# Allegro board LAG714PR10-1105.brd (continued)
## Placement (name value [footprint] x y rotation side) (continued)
RW5  0_0805_5%  [R_0805]  67.98 125.12 270 top
RW6  0_0402_5%  [R_0402]  70.33 132.41 270 top
RW9  0_0402_5%  [R0402_0OHM]  81.12 133.64 90 bottom
RW10  0_0402_5%  [R0402_0OHM]  71.22 132.41 270 top
RW11  0_0402_5%  [R0402_0OHM]  68.28 135.44 0 top
RW12  0_0402_5%  [R0402_0OHM]  71.61 135.44 180 top
RX1  33_0402_5%  [R_0402]  118.63 38.64 180 bottom
RX2  33_0402_5%  [R_0402]  117.55 40.6 180 bottom
RX3  33_0402_5%  [R_0402]  117.59 41.66 180 bottom
RX4  10K_0402_5%  [R_0402]  134.05 55.45 90 bottom
RX5  10K_0402_5%  [R_0402]  113.08 36.95 180 bottom
RX6  0_0402_5%  [R_0402]  115.99 38.46 90 top
RX7  0_0402_5%  [R_0402]  115.1 38.46 90 top
RX8  0_0402_5%  [R_0402]  108.57 39.68 180 bottom
RX9  0_0402_5%  [R_0402]  111.36 36.95 180 bottom
RX10  0_0402_5%  [R_0402]  108.57 40.51 180 bottom
RZ1  22.1K_0402_1%  [R_0402]  151.51 66.88 90 top
RZ2  0_0402_5%  [R_0402]  149.98 55.84 0 top
RZ3  49.9K_0402_1%  [R_0402]  150.05 56.78 90 top
RZ4  0_0603_5%  [R_0603]  148.13 69.57 180 top
SW1  TST71-N-220-T170-S017_2P  [SW_TST71-N-220-T170-S017_2P]  221.21 61.99 0 top
TL1  MHPC_NS681611H  [BOTH_NS0013LF_16P]  17.03 73.13 270 top
TL2  MHPC_NS681611H  [BOTH_NS0013LF_16P]  17.03 64.24 90 bottom
TP3  PAD  [TPC12]  108.92 93.28 180 bottom
TP4  PAD  [TPC12]  109.99 94.1 180 bottom
TP5  PAD  [TPC12]  119.58 90.57 0 top
TP6  PAD  [TPC12]  118.31 90.6 0 top
TP7  PAD  [TPC12]  139.05 105.14 180 bottom
TP8  PAD  [TPC12]  133.92 83.16 0 top
TP9  PAD  [TPC12]  133.52 84.44 0 top
TP10  PAD  [TPC12]  117.16 67.72 0 top
TP11  PAD  [TPC12]  110.32 69.25 180 bottom
TP12  PAD  [TPC12]  111.91 64.84 180 bottom
TP13  PAD  [TPC12]  120.28 64.83 0 top
TP14  PAD  [TPC12]  141.41 94.93 180 bottom
TP15  PAD  [TPC12]  137.96 90.66 180 bottom
TP16  PAD  [TPC12]  139.43 89.14 180 bottom
TP17  PAD  [TPC12]  137.98 89.31 180 bottom
TP18  PAD  [TPC12]  139.23 90.41 180 bottom
TP19  PAD  [TPC12]  112.3 103.48 180 bottom
TP20  PAD  [TPC12]  109.39 103.63 180 bottom
TP21  PAD  [TPC12]  109.98 102.34 180 bottom
TP22  PAD  [TPC12]  110.77 104.07 180 bottom
TP23  PAD  [TPC12]  121.98 66.86 0 top
TP24  PAD  [TPC12]  121.65 64.91 0 top
TP25  PAD  [TPC12]  116.97 56.86 180 bottom
TP26  PAD  [TPC12]  117.67 62.38 0 top
TP27  PAD  [TPC12]  110.61 57.82 180 bottom
TP28  PAD  [TPC12]  116.37 62.82 0 top
TP29  PAD  [TPC12]  116.43 61.45 0 top
TP30  PAD  [TPC12]  115.1 103.49 180 bottom
TP31  PAD  [TPC12]  113.75 103.61 180 bottom
TP32  PAD  [TPC12]  131.45 78.06 0 top
TP33  PAD  [TPC12]  121.32 77.83 0 top
TP38  PAD  [TPC12]  119.66 72.31 0 top
TP39  PAD  [TPC12]  120.73 71.45 0 top
TP44  PAD  [TPC12]  27.97 68.13 0 top
TP46  PAD  [TPC12]  196.2 62.49 180 bottom
TP48  PAD  [TPC12]  19.11 88.76 90 top
TP49  PAD  [TPC12]  22.2 87.37 90 bottom
TP74  PAD  [TPC12]  92.05 51.54 0 top
TP75  PAD  [TPC12]  120.82 68.64 0 top
TP76  PAD  [TPC12]  119.24 65.59 0 top
TP77  PAD  [TPC12]  119.59 67.76 0 top
TP79  PAD  [TPC12]  124.79 57.51 180 bottom
TPC1  PAD  [TPC12]  140.46 90.84 270 bottom
TPC2  PAD  [TPC12]  138.62 93.31 180 bottom
TPC3  PAD  [TPC12]  139.15 91.78 180 bottom
TPC4  PAD  [TPC12]  140.45 92.24 180 bottom
TPC5  PAD  [TPC12]  145.65 97.9 0 top
TPC6  PAD  [TPC12]  137.98 94.5 180 bottom
TPC7  PAD  [TPC12]  139.98 62.16 180 bottom
TPC8  PAD  [TPC12]  109.88 54.57 180 bottom
TPC9  PAD  [TPC12]  113.37 54.44 180 bottom
TPC10  PAD  [TPC12]  139.53 100.54 180 bottom
TPC11  PAD  [TPC12]  139.51 101.84 180 bottom
TPC12  PAD  [TPC12]  133.26 99.83 0 top
TPC13  PAD  [TPC12]  140.8 105.14 180 bottom
TPC14  PAD  [TPC12]  134.07 102.6 0 top
TPC15  PAD  [TPC12]  136.69 105.06 180 bottom
TPC16  PAD  [TPC12]  135.75 104.2 180 bottom
TPC17  PAD  [TPC12]  136.61 103.26 180 bottom
TPC18  PAD  [TPC12]  132.52 97.39 0 top
TPC19  PAD  [TPC12]  132.93 96.12 0 top
TPC20  PAD  [TPC12]  134.76 105.01 180 bottom
TPC21  PAD  [TPC12]  133 102.45 180 bottom
TPC22  PAD  [TPC12]  134.83 103.31 180 bottom
TPC23  PAD  [TPC12]  133.49 104.86 180 bottom
TPC24  PAD  [TPC12]  131.68 102.4 180 bottom
TPC25  PAD  [TPC12]  132.22 105.11 180 bottom
TPC26  PAD  [TPC12]  132.24 103.56 180 bottom
TPC27  PAD  [TPC12]  133.59 103.59 180 bottom
TPC28  PAD  [TPC12]  133.84 98.69 0 top
TPC29  PAD  [TPC12]  134.12 97.32 0 top
TPC30  PAD  [TPC12]  133.92 94.32 0 top
TPC31  PAD  [TPC12]  137.91 92.21 180 bottom
TPC32  PAD  [TPC12]  101 60.19 0 top
TPC33  PAD  [TPC12]  141.13 102.48 180 bottom
TPS1  PAD  [TPC12]  139.95 60.36 180 bottom
TPS2  PAD  [TPC12]  118.5 66.89 0 top
TPS3  PAD  [TPC12]  149.53 51.09 0 top
TPS4  PAD  [TPC12]  108.77 68.77 180 bottom
TPS5  PAD  [TPC12]  95.35 40.57 0 top
TPS6  PAD  [TPC12]  118.61 69.53 0 top
TPS8  PAD  [TPC12]  223.43 65.67 0 top
U1  -  [SY6288C20AAC_SOT23-5]  220.06 55.87 0 top
U2  -  [NCT7718W_MSOP8]  103.36 123.83 90 bottom
U3  -  [SY6288C20AAC_SOT23-5]  210.41 42.8 0 top
UA1  -  [ALC3246-CG_MQFN48_6X6]  32.83 11.05 180 top
UC1  SKL-U_BGA1356  [SKL-U_BGA_1356P-T]  136.55 59.59 270 bottom
UC2  -  [74AUP1G07GW_TSSOP5]  106.24 117.23 90 top
UC3  W25Q128JVSIQ_SO8  [W25Q128FVSIQ_SO8]  129.74 45.31 270 bottom
UC4  -  [SN74AHC1G08DCKR_SC70-5]  120.37 44.61 180 bottom
UC5  -  [SN74AHC1G08DCKR_SC70-5]  98.76 55.11 0 top
UC6  -  [74AUP1G07GW_TSSOP5]  121.69 39.19 270 top
UC7  -  [74AUP1G07GW_TSSOP5]  145.88 104.36 180 top
UC9  -  [SN74AHC1G08DCKR_SC70-5]  149.53 52.54 0 top
UE1  -  [MEC1416-NU-D0_VTQFP128_14X14]  33.58 75.63 0 top
UE2  -  [NL17SZ06DFT2G_SC70-5]  48.18 57.43 0 top
UL1  RTL8106E-CG_QFN32_4X4  [RTL8106E-CG_QFN32_4X4-S]  23.08 83.54 0 top
UL2  -  [SY6288C20AAC_SOT23-5]  24.74 97.92 0 top
UM1  THGBMBG8D4KBAIR_VFBGA153  [THGBMBG8D4KBAIRNHDI_VFBGA_153P]  144.52 34.11 90 top
UM2  -  [74AUP1G07GW_TSSOP5]  152.54 28.52 90 top
US1  -  [LNG2DMTR_LGA12_2X2]  190.45 40.77 180 top
US2  -  [SY6288D20AAC_SOT23-5]  178.97 36.96 180 bottom
UU1  -  [SY6288D20AAC_SOT23-5]  20.17 42.67 90 bottom
UU3  -  [SY6288D20AAC_SOT23-5]  198.96 38.86 180 bottom
UX1  -  [NPCT650VB2YX_QFN32_5X5]  110.1 39.17 0 bottom
UZ1  TPS22967DSGR_SON8_2X2  [TPS22967DSGR_SON8_2X2-S]  149.25 66.01 90 top
UZ2  EM5201V DFN3X3 8P  [TPS22961DNYR_WSON8]  148.93 59.19 90 top
UZ3  -  [EM5209VF_DFN14_3X2]  128.17 136.49 180 top
YC1  24MHZ_12PF_X3G024000DC1H  [Y_X3G024000DC1H_4P]  143.93 77.54 90 bottom
YC2  32.768KHZ_9PF_X1A000141000200  [Y_X1A000141000200_2P]  105.84 57.11 180 top
YC3  24MHZ_12PF_X3G024000DC1H  [Y_X3G024000DC1H_4P]  146.65 55.36 270 bottom
YE1  32.768KHZ_9PF_X1A000141000200  [Y_X1A000141000200_2P]  37.76 82.32 180 top
YL1  25MHZ_10PF_7V25000014  [Y_7V25000014_4P]  16.2 87.41 270 top

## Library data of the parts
C1-C3 C5-C12 C14-C19 C21 C23 C26 C27 C31-C41 CA2 CA4-CA7 CA9 CA10 CA12-CA17 CA20-CA23 CA26-CA31 CA34-CA38 CA40-CA42 CC1-CC5 CC8-CC15 CC26-CC35 CC39-CC58 CC60-CC63 CC67 CC68 CC72 CC73 CC75 CC78 CC79 CC82 CC85-CC88 CC90 CC91 CD3-CD5 CD9-CD18 CD28-CD31 CD35 CD36 CD39-CD48 CD58 CD59 CE1-CE4 CE6-CE17 CE19-CE26 CE28 CE30-CE33 CE35 CI1-CI9 CL1-CL12 CL15 CL18-CL20 CL22-CL25 CM1-CM8 CS1-CS6 CS8-CS14 CS16-CS23 CS25-CS27 CS29 CT55-CT60 CU1-CU4 CU6 CU11 CW1-CW4 CW6-CW9 CX1-CX7 CZ1-CZ12 CZ21-CZ23 CZ25 EC2301 EC2302 EC2901 EC2902 EC3001-EC3003 PC1-PC4 PC11-PC15 PC301 PC302 PC305-PC308 PC315 PC501 PC502 PC505-PC508 PC515-PC517 PC1805-PC1807 PC2503-PC2505 PCA03 PCA04 PCA05 PCA06 PCA117 PCA118 PCB01 PCB02 PCB07 PCB08 PCB09-PCB12 PCB14-PCB17 PCB22 PCB25 PCB26 PCB28-PCB32 PCC05 PCC6 PCG05 PCG06 PCG07 PCG08 PCG10 PCG11 PCG147 PCG148 PCH01 PCH02 PCH09-PCH12 PCH14-PCH16 PCI05 PCI06 PCI07 PCI08 PCI10 PCI11 PCI21 PCI22 PCI27 PCI28 PCI30 PCI31 PCI164 PCI165 PCM01 PCM02 PCM11 PCM12 PCM15-PCM19 PCM22 PCM23 PCZ01 PCZ02 PCZ03 PCZ04 PCZ05 PCZ06 PCZ07 PCZ08 PCZ09-PCZ33 PCZ35 PCZ36 = C_0402
C4 C22 C30 CA1 CA3 CA11 CA24 CA25 CA32 CA33 CC36-CC38 CC59 CC76 CC77 CC83 CC84 CD1 CD2 CD6-CD8 CD19-CD26 CD32-CD34 CD37 CD38 CD49-CD56 CE5 CS7 CS15 CS35 CS36 CU8 CU9 CU13 CU14 CU17 CW5 PC309 PC509 PC1801-PC1804 PCA07 PCA08 PCA09 PCA101-PCA109 PCB13 PCB18 PCB27 PCC01 PCC02 PCC03 PCC04 PCG09 PCG12 PCG101-PCG133 PCH05 PCH06 PCH07 PCH08 PCH13 PCI09 PCI12 PCI29 PCI32 PCI101-PCI128 PCM05 PCM06 PCM07 PCM08 PCM09 PCM10 PCM13 PCM14 PCM20 PCM21 PCZ34 = C_0603
CC6 CC7 CC17 CC18 CC69-CC71 CU5 CU16 PCA110-PCA116 PCG134-PCG146 PCI129-PCI163 = C_0201
CD27 PCG171 PCG172 PCI171-PCI173 = C_D2
CL13 = C_1206
CS24 CS30 CS33 CS34 PC303 PC304 PC310-PC314 PC503 PC504 PC510-PC514 PC2501 PC2502 PCA01 PCA02 PCB03 PCB04 PCB05 PCB06 PCB19-PCB21 PCB23 PCB24 PCG01 PCG02 PCG03 PCG04 PCH03 PCH04 PCI01 PCI02 PCI03 PCI04 PCI23-PCI26 PCM03 PCM04 = C_0805
CU10 CU15 = C_A
D1 = BAS40C_SOT23-3
D3 D4 DA3 = BAT54C-7-F_SOT23-3
D5 D6 = RB551V-30_SOD323-2
D7 DZ2-DZ5 = RB751S40T1G_SOD523-2
DA1 DA2 DA4 DA7 ED2901 = L03ESDL5V0CC3-2_SOT23-3
DA5 = AZ5123-02SPR7G_SOT23-3
DA6 EU2602 EU2604 EU2701 EU4012 = AZC199-02SPR7G_SOT23-3
DE1 = AZ5125-01HPR7G_SOD523-2
DI1 = BAW56W_SOT323-3
EU2601 EU2603 = L05ESDL5V0NA-4_SLP2510P8-10-9
F1 = F_SMD1812P150TF-24
F2 = F_SMD1812P110TF-24
F3 = F_MF-NSMF050-2
FD1-FD4 = FIDUCIAL_C40M80
FI1 = F_1206L150PR
H1-H5 H7 = H_3P0
H6 = H_5P0
H8 = H_3P3
H12 = H_3P2
H13 = H_3P0X4P0
H14 = H_5P6N
HCPU1 HCPU4 = H_4P0X3P7
HCPU2 = H_3P7
HCPU3 = H_4P0
JCMOS1 = SHORTPADS: User Part Number: PART#
JDEG1 JESPI1 = JXT_FP241AH-010GAAM_10P
JDIMM1 = LOTES_ADDR0206-P001A02_260P
JDIMM2 = LOTES_ADDR0205-P001A02_260P
JEDP1 = ACES_51540-04001-P01_40P
JFAN1 JSPK1 = ACES_50224-00401-001_4P
JFP = ACES_51522-00601-001_6P-NPM
JFP1 = ACES_51522-00801-001_8P
JHDD1 = ACES_51625-01201-001_12P
JHDMI1 = ACON_HMRF6-AK120C_19P-T
JHP1 = YUQIU_PJ753-F07J1BE-B_7P-T
JIOB1 = ACES_51524-0160N-001_16P
JKB1 = HEFEN_AFB02-S30F1A-HF_30P-T
JKBBL1 = ACES_51575-00401-001_4P
JLAN1 = SINGA_2RJ3076-078211F_8P-T
JODD1 = ACES_50673-0120N-P01_12P
JP1 JP5 JP6 JP10 PJP2 PJP501 PJP1802 PJPG01 = JUMP_43X79
JP2 JP4 JP11 PJP301 PJP1801 PJP2501 PJP2502 PJPA01 PJPH01 PJPM01 PJPM03 = JUMP_43X39
JPWR1 = JXT_FP226H-004S1AM_4P
JSSD1 = LCN_DAN05-67306-0103_75P
JTP1 = ACES_51524-0080N-001_8P
JUSB1 JUSB2 = ACON_TARAN-9R1391_9P
JVGA = ACES_51625-01601-001_16P-T
JWLAN1 = LCN_DAN05-67306-0100_75P
L1 L2 = MURAT_BLM15BD601SN1D_2P
L3 LU1 LU4 LU8 LU9 = INPAQ_MCM1012B900F06BP_4P
L4 = INPAQ_MCM1012B900F06BP_4P-NPM
L5 = MURAT_BLM15PX221SN1D_2P
LED1 = LED_LTW-295DSKS-5A_4P
LI1-LI4 LU2 LU3 LU5 LU6 = INPAQ_HCM1012GH900BP_4P-NPM
PBATT1 = ACES_50458-01001-P01_10P-T
PCG13 PCI13 = C_EEFCX1E330R
PCG14 PCI14 = C_6P3X4P5-NPM
PD1 PD5 PD6 = TVNST52302AB0_SOT523-3
PD2 PD3 = BAV99W_SC70-3
PD501 = SDMK0340L-7-F_SOD323-2
PDB01 = LRB715FT1G_SOT323-3
PHZ01 PHZ02 PHZ03 PHZ04 PHZ05 PR1 PR3-PR7 PR31 PR33-PR45 PR302-PR304 PR306-PR308 PR504 PR506 PR508-PR511 PR1802 PR1803 PR1805 PR1807 PR2502-PR2504 PRB03 PRB04 PRB06 PRB07 PRB08 PRB09-PRB11 PRB13 PRB14 PRB19-PRB21 PRB24 PRB25 PRB29-PRB40 PRB42 PRB43 PRG02 PRH02 PRH03 PRH04 PRH05 PRH08 PRH09 PRH11 PRH12 PRI02 PRI22 PRM03 PRM06 PRM07 PRM10 PRM11 PRZ01 PRZ04 PRZ05 PRZ06 PRZ08 PRZ10 PRZ11 PRZ15 PRZ16 PRZ19-PRZ21 PRZ23 PRZ24 PRZ26-PRZ28 PRZ30-PRZ33 PRZ35-PRZ43 PRZ45 PRZ46 PRZ48-PRZ52 PRZ55-PRZ58 PRZ60 PRZ61 PRZ64-PRZ69 R1 R2 R5 R9 R10 R19-R35 R38-R43 R46-R50 R57 R65-R69 R72 R74-R76 R78-R80 RA3 RA7-RA12 RA23-RA34 RA41-RA43 RC1-RC12 RC14 RC15 RC18-RC28 RC33-RC42 RC44-RC47 RC51-RC58 RC63-RC69 RC72-RC78 RC80 RC82 RC85-RC96 RC102-RC105 RC108-RC115 RC117-RC134 RC136-RC148 RC150-RC157 RC159 RC160 RC163 RC164 RC175-RC182 RC188 RC194-RC199 RC205 RC207 RC209 RC211-RC213 RC224 RC443 RD1-RD3 RD7 RD9-RD13 RD15 RD17 RD19-RD24 RE1 RE3 RE4 RE6 RE8-RE21 RE23 RE25 RE29 RE32 RE40 RE41 RE43 RE45 RE46 RE48 RE49 RE51-RE59 RE62 RE65 RE67 RE68 RE70 RE91 RE92 RH1 RI1-RI16 RL2-RL4 RL6-RL9 RL17 RM3 RM12-RM25 RM27 RS2-RS5 RU3-RU6 RU9-RU12 RW6 RX1-RX10 RZ1-RZ3 = R_0402
PJP1 PJP3 PJPI01 = JUMP_43X79-NPM
PJP302 PJP502 PJPH02 PJPM02 = JUMP_43X118
PJPB01 = JUMP_43X118-NPM
PJPDC1 = ACES_50458-00601-001_6P-T
PL1 PL4 PL511 PLB02 PLG11 PLI11 = 5A_Z150_1210_2P
PL2 = 5A_Z150_1210_2P-NPM
PL3 = MURAT_BLM15AG102SN1D_2P
PL301 PL501 PLB01 PLH01 PLM01 = L_7X7X3_M_2P
PL311 PL1811 PLH11 PLM11 = TAI-T_HCB2012KF-121T50_2P
PL1801 = L_5X5X3_M_2P
PLA01 = L_5X5X3_M
PLG01 PLI01 PLI02 = L_7X7X4_M
PQ1 = FDV301N-G_SOT23-3
PQ2 = MMST3904-7-F_SOT323-3
PQ11 PQB03 PQB04 QI3 = DMN65D8LW-7_SOT323-3
PQ12 PQ13 = DMN65D8LDW-7_SOT363-6
PQA01 PQM01 = AON7934_DFN3X3A8-10
PQB01 PQB02 = AON7702L_DFN8-5
PQB05 PQB06 = RUM002N02GT2L_VMT3
PQB07 = LTC015EUBFS8TL_UMT3F
PQB08 = LMUN5113T1G_SOT323-3
PQB11-PQB13 = TPCA8059-H_PPAK56-8-5
PR32 PR305 PR505 PR1804 PRA02 PRB22 PRB27 PRG03 PRH07 PRI03 PRI23 PRM01 = R_1206
PR301 PR501 PRB12 PRB15 RA4 RA39 RC17 RC169-RC171 RC173 RC174 RE2 RE7 RE50 RE66 RL5 = R0603_0OHM
PR502 PR503 PR507 PR1801 PR2501 PRB05 PRB17 PRB18 PRB23 PRB26 PRB41 PRH01 PRM08 PRM09 PRZ03 PRZ07 PRZ14 PRZ18 PRZ22 PRZ34 PRZ47 PRZ53 PRZ59 PRZ63 R6 R8 R45 R77 RA2 RA5 RA6 RA17 RA18 RA36 RA37 RA40 RC97 RC99 RC106 RC107 RD4-RD6 RD8 RD14 RD16 RD18 RE28 RE37 RE42 RE47 RE60 RE61 RE63 RE81 RL13 RS1 RW9-RW12 = R0402_0OHM
PRA01 PRB16 PRB28 PRG01 PRH06 PRI01 PRI21 PRM02 PRM04 PRM05 PRZ13 PRZ25 PRZ29 PRZ44 R4 R7 R11-R13 R16 R36 R37 RC149 RL1 RL14 RL15 RL19 RL20 RM1 RM2 RZ4 = R_0603
PRB01 PRB02 = R_1206_4P
PRC01 PRC02 PRC03 PRC7 R3 RW3 RW5 = R_0805
PRC04 PRC05 PRC06 = SOLDER_PREFORMS_0603-NPM
PU301 = SY8286BRAC_QFN20_3X3
PU501 = SY8288CRAC_QFN20_3X3
PU1801 = RT8061AZQW_WDFN10_3X3
PU2501 = RT9059GSP_SO8
PUA01 = NCP81253MNTBG_DFN8_2X2
PUB01 = ISL95520HRZ-T_QFN32_4X4-S
PUG01 PUI01 PUI02 = NCP302045MNTXG_PQFN33_5X5
PUH01 = RT6226AGQUF_UQFN12_3X3
PUM01 = RT8207PGQW_WQFN20_3X3
PUZ01 = NCP81218MNTXG_QFN48_6X6
Q1 Q12 Q13 QC2 QI1 = 2N7002K_SOT23-3
Q4 Q24 = L2N7002WT1G_SC-70-3
Q6 Q8 Q9 Q22 QA1 = LN2306LT1G_SOT23-3
Q7 Q18 Q19 = DDTA144VCA-7-F_SOT23-3
Q10 Q11 Q17 Q25 QC1 QI2 QS1 = DMN66D0LDW-7_SOT363-6
Q14 = LMBT3904LT1G_SOT23-3
Q15 = SI2301CDS-T1-GE3_SOT23-3
Q23 = LP2301ALT1G_SOT23-3
R17 R18 RU1 RU2 RU7 RU8 RU13-RU16 = R_0402-NPM
RA1 RA22 = R0805_0OHM
RA13-RA16 = MURAT_BLM15PD600SN1D_2P
RA35 RA38 = MURAT_BLM15PX330SN1D_2P
RP1 RP2 RPC1-RPC3 RPE1-RPE7 RPI1 RPI2 RPM1 RPM2 = RP_0804_8P4R
SW1 = SW_TST71-N-220-T170-S017_2P
TL1 TL2 = BOTH_NS0013LF_16P
TP3-TP33 TP38 TP39 TP44 TP46 TP48 TP49 TP74-TP77 TP79 TPC1-TPC33 TPS1-TPS6 TPS8 = TPC12
U1 U3 UL2 = SY6288C20AAC_SOT23-5
U2 = NCT7718W_MSOP8
UA1 = ALC3246-CG_MQFN48_6X6
UC1 = SKL-U_BGA_1356P-T
UC2 UC6 UC7 UM2 = 74AUP1G07GW_TSSOP5
UC3 = W25Q128FVSIQ_SO8
UC4 UC5 UC9 = SN74AHC1G08DCKR_SC70-5
UE1 = MEC1416-NU-D0_VTQFP128_14X14
UE2 = NL17SZ06DFT2G_SC70-5
UL1 = RTL8106E-CG_QFN32_4X4-S
UM1 = THGBMBG8D4KBAIRNHDI_VFBGA_153P
US1 = LNG2DMTR_LGA12_2X2
US2 UU1 UU3 = SY6288D20AAC_SOT23-5
UX1 = NPCT650VB2YX_QFN32_5X5
UZ1 = TPS22967DSGR_SON8_2X2-S
UZ2 = TPS22961DNYR_WSON8
UZ3 = EM5209VF_DFN14_3X2
YC1 YC3 = Y_X3G024000DC1H_4P
YC2 YE1 = Y_X1A000141000200_2P
YL1 = Y_7V25000014_4P

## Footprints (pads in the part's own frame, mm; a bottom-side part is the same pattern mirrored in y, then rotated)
2N7002K_SOT23-3
  oval 1.016x1.524 smd: 1(0,0) 2(0.965,2.083) 3(-0.965,2.083)
5A_Z150_1210_2P
  rect 0.991x2.997 smd: 1(0,0) 2(2.7,0)
5A_Z150_1210_2P-NPM
  rect 0.991x2.997 smd: 1(0,0) 2(2.7,0)
74AUP1G07GW_TSSOP5
  oval 0.381x1.346 smd: 1(0,0) 2(0.65,0) 3(1.3,0) 4(1.3,1.79) 5(0,1.79)
ACES_50224-00401-001_4P
  oval 0.61x1.549 smd: 1(0,0) 2(1,0) 3(2,0) 4(3,0)
  rect 1.194x1.803 smd: 5(4.3,-3.875) 6(-1.3,-3.875)
ACES_50458-00601-001_6P-T
  oval 0.559x1.6 smd: 1(0,0) 2(2,0) 3(4,0) 4(6,0) 5(8,0) 6(10,0)
  rect 1.295x2.057 smd: 7(-3.1,-5.175) 8(13.1,-5.175)
ACES_50458-01001-P01_10P-T
  oval 0.559x1.803 smd: 1(0,0) 2(2,0) 3(4,0) 4(6,0) 5(8,0) 6(10,0) 7(12,0) 8(14,0) 9(16,0) 10(18,0)
  rect 1.295x2.057 smd: 11(-3.1,-5.275) 12(21.1,-5.275)
ACES_50673-0120N-P01_12P
  oval 0.61x1.397 smd: 1(0,0) 2(0,3) 3(-1,0) 4(-1,3) 5(-2,0) 6(-2,3) 7(-3,0) 8(-3,3) 9(-4,0) 10(-4,3) 11(-5,0) 12(-5,3) 13(-6,0) 14(-6,3) 15(-7,0) 16(-7,3) 17(-8,0) 18(-8,3) 19(-9,0) 20(-9,3) 21(-10,0) 22(-10,3) 23(-11,0) 24(-11,3)
  rect 1.702x2.388 smd: 25(-13.25,1.5) 26(2.25,1.5)
ACES_51522-00601-001_6P-NPM
  oval 0.305x1.295 smd: 1(0,0) 2(0.5,0) 3(1,0) 4(1.5,0) 5(2,0) 6(2.5,0)
  rect 2.489x1.905 smd: 7(-2.15,-3.3) 8(4.65,-3.3)
ACES_51522-00801-001_8P
  oval 0.305x1.295 smd: 1(0,0) 2(0.5,0) 3(1,0) 4(1.5,0) 5(2,0) 6(2.5,0) 7(3,0) 8(3.5,0)
  rect 2.489x1.905 smd: 9(5.65,-3.3) 10(-2.15,-3.3)
ACES_51524-0080N-001_8P
  oval 0.61x1.295 smd: 1(0,0) 2(1,0) 3(2,0) 4(3,0) 5(4,0) 6(5,0) 7(6,0) 8(7,0)
  rect 2.489x2.21 smd: 9(10,-3.05) 10(-3,-3.05)
ACES_51524-0160N-001_16P
  oval 0.61x1.295 smd: 1(0,0) 2(1,0) 3(2,0) 4(3,0) 5(4,0) 6(5,0) 7(6,0) 8(7,0) 9(8,0) 10(9,0) 11(10,0) 12(11,0) 13(12,0) 14(13,0) 15(14,0) 16(15,0)
  rect 2.159x2.21 smd: 17(-2.825,-3.05) 18(17.825,-3.05)
ACES_51540-04001-P01_40P
  oval 0.305x1.092 smd: 1(0,0) 2(0.5,0) 3(1,0) 4(1.5,0) 5(2,0) 6(2.5,0) 7(3,0) 8(3.5,0) 9(4,0) 10(4.5,0) 11(5,0) 12(5.5,0) 13(6,0) 14(6.5,0) 15(7,0) 16(7.5,0) 17(8,0) 18(8.5,0) 19(9,0) 20(9.5,0) 21(10,0) 22(10.5,0) 23(11,0) 24(11.5,0) 25(12,0) 26(12.5,0) 27(13,0) 28(13.5,0) 29(14,0) 30(14.5,0) 31(15,0) 32(15.5,0) 33(16,0) 34(16.5,0) 35(17,0) 36(17.5,0) 37(18,0) 38(18.5,0) 39(19,0) 40(19.5,0)
  rect 0.787x2.489 smd: 41(21.2,-3.6) 42(-1.7,-3.6)
ACES_51575-00401-001_4P
  oval 0.406x0.838 smd: 1(0,0) 2(1,0) 3(2,0) 4(3,0)
  rect 0.787x2.007 smd: 5(-2.2,-3.175) 6(5.2,-3.175)
ACES_51625-01201-001_12P
  oval 0.305x1.092 smd: 1(0,0) 2(0.5,0) 3(1,0) 4(1.5,0) 5(2,0) 6(2.5,0) 7(3,0) 8(3.5,0) 9(4,0) 10(4.5,0) 11(5,0) 12(5.5,0)
  rect 0.991x2.489 smd: 13(-1.8,-3.6) 14(7.3,-3.6)
ACES_51625-01601-001_16P-T
  oval 0.305x1.092 smd: 1(0,0) 2(-0.5,0) 3(-1,0) 4(-1.5,0) 5(-2,0) 6(-2.5,0) 7(-3,0) 8(-3.5,0) 9(-4,0) 10(-4.5,0) 11(-5,0) 12(-5.5,0) 13(-6,0) 14(-6.5,0) 15(-7,0) 16(-7.5,0)
  rect 0.991x2.489 smd: 17(1.8,-3.6) 18(-9.3,-3.6)
ACON_HMRF6-AK120C_19P-T
  round 0.813 hole 0.559: 1(0,0) 2(0.5,1.55) 3(1,0) 4(1.5,1.55) 5(2,0) 6(2.5,1.55) 7(3,0) 8(3.5,1.55) 9(4,0) 10(4.5,1.55) 11(5,0) 12(5.5,1.55) 13(6,0) 14(6.5,1.55) 15(7,0) 16(7.5,1.55) 17(8,0) 18(8.5,1.55) 19(9,0)
  oval 1.499x2.21 hole 0.889x1.6: 20(11.75,1.7) 21(13.65,-7.75) 22(-4.65,-6.5) 23(-2.75,1.7)
ACON_TARAN-9R1391_9P
  round 0.991 hole 0.711: 1(0,0) 2(-2.5,0) 3(-4.5,0) 4(-7,0) 5(-7.5,-1.5) 6(-5.5,-1.5) 7(-3.5,-1.5) 8(-1.5,-1.5) 9(0.5,-1.5)
  oval 1.397x3.2 hole 0.787x2.591: 10(-11.35,-2.38) 12(4.35,-2.38)
  oval 1.397x2.388 hole 0.787x1.803: 11(-11.35,-9.48) 13(4.35,-9.48)
ALC3246-CG_MQFN48_6X6
  oval 0.889x0.203 smd: 1(0,0) 2(0,-0.4) 3(0,-0.8) 4(0,-1.2) 5(0,-1.6) 6(0,-2) 7(0,-2.4) 8(0,-2.8) 9(0,-3.2) 10(0,-3.6) 11(0,-4) 12(0,-4.4) 25(6.1,-4.4) 26(6.1,-4) 27(6.1,-3.6) 28(6.1,-3.2) 29(6.1,-2.8) 30(6.1,-2.4) 31(6.1,-2) 32(6.1,-1.6) 33(6.1,-1.2) 34(6.1,-0.8) 35(6.1,-0.4) 36(6.1,0)
  oval 0.203x0.889 smd: 13(0.85,-5.25) 14(1.25,-5.25) 15(1.65,-5.25) 16(2.05,-5.25) 17(2.45,-5.25) 18(2.85,-5.25) 19(3.25,-5.25) 20(3.65,-5.25) 21(4.05,-5.25) 22(4.45,-5.25) 23(4.85,-5.25) 24(5.25,-5.25) 37(5.25,0.85) 38(4.85,0.85) 39(4.45,0.85) 40(4.05,0.85) 41(3.65,0.85) 42(3.25,0.85) 43(2.85,0.85) 44(2.45,0.85) 45(2.05,0.85) 46(1.65,0.85) 47(1.25,0.85) 48(0.85,0.85)
  rect 4.394x4.394 smd: 49(3.05,-2.2)
AON7702L_DFN8-5
  oval 0.406x0.991 smd: 1(0,0) 2(0.66,0) 3(1.32,0) 4(1.98,0)
  custom 0.559x0.559 smd: 5(0.99,2.247)
AON7934_DFN3X3A8-10
  oval 0.457x0.508 smd: 1(0,0) 2(0.65,0) 3(1.3,0) 4(1.95,0) 5(1.95,2.76) 6(1.3,2.76) 7(0.65,2.76) 8(0,2.76)
  rect 2.54x1.041 smd: 9(0.975,1.813)
  rect 2.54x0.559 smd: 10(0.975,0.708)
AZ5123-02SPR7G_SOT23-3
  oval 1.016x1.524 smd: 1(0,0) 2(0.965,2.083) 3(-0.965,2.083)
AZ5125-01HPR7G_SOD523-2
  rect 0.61x0.787 smd: 1(0,0) 2(1.5,0)
AZC199-02SPR7G_SOT23-3
  oval 1.016x1.524 smd: 1(0,0) 2(0.965,2.083) 3(-0.965,2.083)
BAS40C_SOT23-3
  oval 1.016x1.524 smd: 1(0,0) 2(0.965,2.083) 3(-0.965,2.083)
BAT54C-7-F_SOT23-3
  oval 1.016x1.524 smd: 1(0,0) 2(0.965,2.083) 3(-0.965,2.083)
BAV99W_SC70-3
  oval 0.508x0.559 smd: 1(0,0) 2(-0.65,-1.85) 3(0.65,-1.85)
BAW56W_SOT323-3
  oval 0.813x0.914 smd: 1(0,0) 2(0.65,1.6) 3(-0.65,1.6)
BOTH_NS0013LF_16P
  oval 0.762x1.905 smd: 1(0,0) 2(1.27,0) 3(2.54,0) 4(3.81,0) 5(5.08,0) 6(6.35,0) 7(7.62,0) 8(8.89,0) 9(8.89,8.8) 10(7.62,8.8) 11(6.35,8.8) 12(5.08,8.8) 13(3.81,8.8) 14(2.54,8.8) 15(1.27,8.8) 16(0,8.8)
C_6P3X4P5-NPM
  oval 3.505x1.6 smd: 1(0,0) 2(5.6,0)
C_0201
  rect 0.381x0.356 smd: 1(0,0) 2(0.584,0)
C_0402
  rect 0.508x0.584 smd: 1(0,0) 2(0.914,0)
C_0603
  rect 0.635x0.889 smd: 1(0,0) 2(1.397,0)
C_0805
  rect 0.813x1.397 smd: 1(0,0) 2(1.702,0)
C_1206
  rect 1.016x1.778 smd: 1(0,0) 2(2.667,0)
C_A
  rect 1.626x1.829 smd: 1(0.389,0) 2(2.989,0)
C_D2
  rect 2.388x2.794 smd: 1(0,0) 2(6.4,0)
C_EEFCX1E330R
  rect 2.388x2.794 smd: 1(0,0) 2(-6.4,0)
DDTA144VCA-7-F_SOT23-3
  oval 1.016x1.524 smd: 1(0,0) 2(0.965,2.083) 3(-0.965,2.083)
DMN65D8LDW-7_SOT363-6
  oval 0.432x0.61 smd: 1(0,0) 2(0.65,0) 3(1.3,0) 4(1.3,1.9) 5(0.65,1.9) 6(0,1.9)
DMN65D8LW-7_SOT323-3
  oval 0.711x0.889 smd: 1(0,0) 2(-0.65,-1.9) 3(0.65,-1.9)
DMN66D0LDW-7_SOT363-6
  oval 0.432x0.61 smd: 1(0,0) 2(0.65,0) 3(1.3,0) 4(1.3,1.9) 5(0.65,1.9) 6(0,1.9)
EM5209VF_DFN14_3X2
  oval 0.203x0.711 smd: 1(0,0) 2(0.4,0) 3(0.8,0) 4(1.2,0) 5(1.6,0) 6(2,0) 7(2.4,0) 8(2.4,2) 9(2,2) 10(1.6,2) 11(1.2,2) 12(0.8,2) 13(0.4,2) 14(0,2)
  rect 2.591x0.991 smd: 15(1.2,1)
F_1206L150PR
  rect 0.991x1.803 smd: 1(0,0) 2(2.8,0)
F_MF-NSMF050-2
  rect 0.991x1.6 smd: 1(0,0) 2(3,0)
F_SMD1812P110TF-24
  rect 1.778x3.15 smd: 1(0,0) 2(5.23,0)
F_SMD1812P150TF-24
  rect 1.778x3.15 smd: 1(0,0) 2(5.23,0)
FDV301N-G_SOT23-3
  oval 1.016x1.524 smd: 1(0,0) 2(0.965,2.083) 3(-0.965,2.083)
FIDUCIAL_C40M80
  round 1.016 smd: 1(0,0)
H_3P0
  round 3.505 hole 2.997: 1(0,0)
H_3P0X4P0
  oval 3.505x4.496 hole 2.997x3.988: 1(0,0)
H_3P2
  round 3.708 hole 3.2: 1(0,0)
H_3P3
  round 3.81 hole 3.302: 1(0,0)
H_3P7
  round 4.216 hole 3.708: 1(0,0)
H_4P0
  round 4.496 hole 3.988: 1(0,0)
H_4P0X3P7
  oval 4.496x4.216 hole 3.988x3.708: 1(0,0)
H_5P0
  round 5.512 hole 5.004: 1(0,0)
H_5P6N
  round 5.588 hole 5.588 unplated: (0,0)
HEFEN_AFB02-S30F1A-HF_30P-T
  oval 0.229x1.092 smd: 1(0,0) 2(-0.8,0) 3(-1.6,0) 4(-2.4,0) 5(-3.2,0) 6(-4,0) 7(-4.8,0) 8(-5.6,0) 9(-6.4,0) 10(-7.2,0) 11(-8,0) 12(-8.8,0) 13(-9.6,0) 14(-10.4,0) 15(-11.2,0) 16(-12,0) 17(-12.8,0) 18(-13.6,0) 19(-14.4,0) 20(-15.2,0) 21(-16,0) 22(-16.8,0) 23(-17.6,0) 24(-18.4,0) 25(-19.2,0) 26(-20,0) 27(-20.8,0) 28(-21.6,0) 29(-22.4,0) 30(-23.2,0)
  rect 0.559x1.295 smd: 31(1.475,-3.45) 32(-24.675,-3.45)
INPAQ_HCM1012GH900BP_4P-NPM
  rect 0.711x0.305 smd: 1(0,0) 2(1.25,0) 3(1.25,-0.5) 4(0,-0.5)
INPAQ_MCM1012B900F06BP_4P
  rect 0.711x0.305 smd: 1(0,0) 2(1.25,0) 3(1.25,-0.5) 4(0,-0.5)
INPAQ_MCM1012B900F06BP_4P-NPM
  rect 0.711x0.305 smd: 1(0,0) 2(1.25,0) 3(1.25,-0.5) 4(0,-0.5)
ISL95520HRZ-T_QFN32_4X4-S
  oval 0.889x0.203 smd: 1(0,0) 2(0,-0.4) 3(0,-0.8) 4(0,-1.2) 5(0,-1.6) 6(0,-2) 7(0,-2.4) 8(0,-2.8) 17(4.1,-2.8) 18(4.1,-2.4) 19(4.1,-2) 20(4.1,-1.6) 21(4.1,-1.2) 22(4.1,-0.8) 23(4.1,-0.4) 24(4.1,0)
  oval 0.203x0.889 smd: 9(0.65,-3.45) 10(1.05,-3.45) 11(1.45,-3.45) 12(1.85,-3.45) 13(2.25,-3.45) 14(2.65,-3.45) 15(3.05,-3.45) 16(3.45,-3.45) 25(3.45,0.65) 26(3.05,0.65) 27(2.65,0.65) 28(2.25,0.65) 29(1.85,0.65) 30(1.45,0.65) 31(1.05,0.65) 32(0.65,0.65)
  rect 2.642x2.642 smd: 33(2.05,-1.4)
JUMP_43X39
  custom 0.191x0.191 smd: 1(0,0) 2(0.914,0)
JUMP_43X79
  custom 0.188x0.188 smd: 1(0,0) 2(1.1,0)
JUMP_43X79-NPM
  custom 0.188x0.188 smd: 1(0,0) 2(1.1,0)
JUMP_43X118
  custom 0.187x0.187 smd: 1(0,0) 2(1.1,0)
JUMP_43X118-NPM
  custom 0.187x0.187 smd: 1(0,0) 2(1.1,0)
JXT_FP226H-004S1AM_4P
  oval 0.61x1.295 smd: 1(0,0) 2(1,0) 3(2,0) 4(3,0)
  rect 0.991x2.007 smd: 5(-2.6,-3.25) 6(5.6,-3.25)
JXT_FP241AH-010GAAM_10P
  oval 0.305x1.092 smd: 1(0,0) 2(0.5,0) 3(1,0) 4(1.5,0) 5(2,0) 6(2.5,0) 7(3,0) 8(3.5,0) 9(4,0) 10(4.5,0)
  rect 0.406x0.787 smd: 11(-1,-2.65) 12(5.5,-2.65)
L2N7002WT1G_SC-70-3
  oval 0.711x0.889 smd: 1(0,0) 2(-0.65,-1.9) 3(0.65,-1.9)
L03ESDL5V0CC3-2_SOT23-3
  oval 1.016x1.524 smd: 1(0,0) 2(0.965,2.083) 3(-0.965,2.083)
L05ESDL5V0NA-4_SLP2510P8-10-9
  rect 0.203x0.686 smd: 1(0,0) 2(-0.5,0) 4(-1.5,0) 5(-2,0) 6(-2,-0.875) 7(-1.5,-0.875) 8(-0.5,-0.875) 9(0,-0.875)
  rect 0.406x1.549 smd: 3(-1,-0.437)
L_5X5X3_M
  custom 0.54x0.54 smd: 1(0,0) 4(4.35,0)
  rect 0.762x0.508 smd: 2(0.699,0) 3(3.652,0)
L_5X5X3_M_2P
  rect 2.159x2.794 smd: 1(0,0) 2(4.35,0)
L_7X7X3_M_2P
  rect 2.362x3.505 smd: 1(0,0) 2(6.05,0)
L_7X7X4_M
  custom 0.591x0.591 smd: 1(0,0) 4(6.05,0)
  rect 0.762x0.508 smd: 2(0.8,0) 3(5.25,0)
LCN_DAN05-67306-0100_75P
  round 1.092 hole 1.092 unplated: (-0.75,-5.275)
  round 1.6 hole 1.6 unplated: (19.25,-5.275)
  oval 0.305x1.549 smd: 1(0,0) 2(0.25,-7.55) 3(0.5,0) 4(0.75,-7.55) 5(1,0) 6(1.25,-7.55) 7(1.5,0) 16(3.75,-7.55) 17(4,0) 18(4.25,-7.55) 19(4.5,0) 20(4.75,-7.55) 21(5,0) 22(5.25,-7.55) 23(5.5,0) 24(5.75,-7.55) 25(6,0) 26(6.25,-7.55) 27(6.5,0) 28(6.75,-7.55) 29(7,0) 30(7.25,-7.55) 31(7.5,0) 32(7.75,-7.55) 33(8,0) 34(8.25,-7.55) 35(8.5,0) 36(8.75,-7.55) 37(9,0) 38(9.25,-7.55) 39(9.5,0) 40(9.75,-7.55) 41(10,0) 42(10.25,-7.55) 43(10.5,0) 44(10.75,-7.55) 45(11,0) 46(11.25,-7.55) 47(11.5,0) 48(11.75,-7.55) 49(12,0) 50(12.25,-7.55) 51(12.5,0) 52(12.75,-7.55) 53(13,0) 54(13.25,-7.55) 55(13.5,0) 56(13.75,-7.55) 57(14,0) 58(14.25,-7.55) 59(14.5,0) 60(14.75,-7.55) 61(15,0) 62(15.25,-7.55) 63(15.5,0) 64(15.75,-7.55) 65(16,0) 66(16.25,-7.55) 67(16.5,0) 68(16.75,-7.55) 69(17,0) 70(17.25,-7.55) 71(17.5,0) 72(17.75,-7.55) 73(18,0) 74(18.25,-7.55) 75(18.5,0)
  rect 1.194x2.743 smd: 76(19.6,-0.775) 77(-1.1,-0.775)
LCN_DAN05-67306-0103_75P
  round 1.092 hole 1.092 unplated: (-0.75,-5.275)
  round 1.6 hole 1.6 unplated: (19.25,-5.275)
  oval 0.305x1.549 smd: 1(0,0) 2(0.25,-7.55) 3(0.5,0) 4(0.75,-7.55) 5(1,0) 6(1.25,-7.55) 7(1.5,0) 8(1.75,-7.55) 9(2,0) 10(2.25,-7.55) 11(2.5,0) 12(2.75,-7.55) 13(3,0) 14(3.25,-7.55) 15(3.5,0) 16(3.75,-7.55) 17(4,0) 18(4.25,-7.55) 19(4.5,0) 20(4.75,-7.55) 21(5,0) 22(5.25,-7.55) 23(5.5,0) 24(5.75,-7.55) 25(6,0) 26(6.25,-7.55) 27(6.5,0) 28(6.75,-7.55) 29(7,0) 30(7.25,-7.55) 31(7.5,0) 32(7.75,-7.55) 33(8,0) 34(8.25,-7.55) 35(8.5,0) 36(8.75,-7.55) 37(9,0) 38(9.25,-7.55) 39(9.5,0) 40(9.75,-7.55) 41(10,0) 42(10.25,-7.55) 43(10.5,0) 44(10.75,-7.55) 45(11,0) 46(11.25,-7.55) 47(11.5,0) 48(11.75,-7.55) 49(12,0) 50(12.25,-7.55) 51(12.5,0) 52(12.75,-7.55) 53(13,0) 54(13.25,-7.55) 55(13.5,0) 56(13.75,-7.55) 57(14,0) 58(14.25,-7.55) 67(16.5,0) 68(16.75,-7.55) 69(17,0) 70(17.25,-7.55) 71(17.5,0) 72(17.75,-7.55) 73(18,0) 74(18.25,-7.55) 75(18.5,0)
  rect 1.194x2.743 smd: 76(19.6,-0.775) 77(-1.1,-0.775)
LED_LTW-295DSKS-5A_4P
  rect 0.508x0.406 smd: 1(0,0) 2(1.2,0) 3(0,0.7) 4(1.2,0.7)
LMBT3904LT1G_SOT23-3
  oval 1.016x1.524 smd: 1(0,0) 2(0.965,2.083) 3(-0.965,2.083)
LMUN5113T1G_SOT323-3
  oval 0.711x0.889 smd: 1(0,0) 2(0.65,1.9) 3(-0.65,1.9)
LN2306LT1G_SOT23-3
  oval 1.016x1.524 smd: 1(0,0) 2(0.965,2.083) 3(-0.965,2.083)
LNG2DMTR_LGA12_2X2
  oval 0.406x0.305 smd: 1(0,0) 4(0,-1.5) 7(1.602,-1.5) 10(1.602,0)
  oval 0.508x0.305 smd: 2(0.051,-0.5) 3(0.051,-1) 8(1.551,-1) 9(1.551,-0.5)
  oval 0.305x0.508 smd: 5(0.551,-1.5) 6(1.051,-1.5) 11(1.051,0) 12(0.551,0)
LOTES_ADDR0205-P001A02_260P
  round 1.6 hole 1.6 unplated: (-1.025,4.1)
  round 1.092 hole 1.092 unplated: (67.775,4.1)
  oval 0.305x1.753 smd: 1(0,0) 2(0.25,8.2) 3(0.5,0) 4(0.75,8.2) 5(1,0) 6(1.25,8.2) 7(1.5,0) 8(1.75,8.2) 9(2,0) 10(2.25,8.2) 11(2.5,0) 12(2.75,8.2) 13(3,0) 14(3.25,8.2) 15(3.5,0) 16(3.75,8.2) 17(4,0) 18(4.25,8.2) 19(4.5,0) 20(4.75,8.2) 21(5,0) 22(5.25,8.2) 23(5.5,0) 24(5.75,8.2) 25(6,0) 26(6.25,8.2) 27(6.5,0) 28(6.75,8.2) 29(7,0) 30(7.25,8.2) 31(7.5,0) 32(7.75,8.2) 33(8,0) 34(8.25,8.2) 35(8.5,0) 36(8.75,8.2) 37(9,0) 38(9.25,8.2) 39(9.5,0) 40(9.75,8.2) 41(10,0) 42(10.25,8.2) 43(10.5,0) 44(10.75,8.2) 45(11,0) 46(11.25,8.2) 47(11.5,0) 48(11.75,8.2) 49(12,0) 50(12.25,8.2) 51(12.5,0) 52(12.75,8.2) 53(13,0) 54(13.25,8.2) 55(13.5,0) 56(13.75,8.2) 57(14,0) 58(14.25,8.2) 59(14.5,0) 60(14.75,8.2) 61(15,0) 62(15.25,8.2) 63(15.5,0) 64(15.75,8.2) 65(16,0) 66(16.25,8.2) 67(16.5,0) 68(16.75,8.2) 69(17,0) 70(17.25,8.2) 71(17.5,0) 72(17.75,8.2) 73(18,0) 74(18.25,8.2) 75(18.5,0) 76(18.75,8.2) 77(19,0) 78(19.25,8.2) 79(19.5,0) 80(19.75,8.2) 81(20,0) 82(20.25,8.2) 83(20.5,0) 84(20.75,8.2) 85(21,0) 86(21.25,8.2) 87(21.5,0) 88(21.75,8.2) 89(22,0) 90(22.25,8.2) 91(22.5,0) 92(22.75,8.2) 93(23,0) 94(23.25,8.2) 95(23.5,0) 96(23.75,8.2) 97(24,0) 98(24.25,8.2) 99(24.5,0) 100(24.75,8.2) 101(25,0) 102(25.25,8.2) 103(25.5,0) 104(25.75,8.2) 105(26,0) 106(26.25,8.2) 107(26.5,0) 108(26.75,8.2) 109(27,0) 110(27.25,8.2) 111(27.5,0) 112(27.75,8.2) 113(28,0) 114(28.25,8.2) 115(28.5,0) 116(28.75,8.2) 117(29,0) 118(29.25,8.2) 119(29.5,0) 120(29.75,8.2) 121(30,0) 122(30.25,8.2) 123(30.5,0) 124(30.75,8.2) 125(31,0) 126(31.25,8.2) 127(31.5,0) 128(31.75,8.2) 129(32,0) 130(32.25,8.2) 131(32.5,0) 132(32.75,8.2) 133(33,0) 134(33.25,8.2) 135(33.5,0) 136(33.75,8.2) 137(34,0) 138(34.25,8.2) 139(34.5,0) 140(34.75,8.2) 141(35,0) 142(35.25,8.2) 143(35.5,0) 144(35.75,8.2) 145(38,0) 146(38.25,8.2) 147(38.5,0) 148(38.75,8.2) 149(39,0) 150(39.25,8.2) 151(39.5,0) 152(39.75,8.2) 153(40,0) 154(40.25,8.2) 155(40.5,0) 156(40.75,8.2) 157(41,0) 158(41.25,8.2) 159(41.5,0) 160(41.75,8.2) 161(42,0) 162(42.25,8.2) 163(42.5,0) 164(42.75,8.2) 165(43,0) 166(43.25,8.2) 167(43.5,0) 168(43.75,8.2) 169(44,0) 170(44.25,8.2) 171(44.5,0) 172(44.75,8.2) 173(45,0) 174(45.25,8.2) 175(45.5,0) 176(45.75,8.2) 177(46,0) 178(46.25,8.2) 179(46.5,0) 180(46.75,8.2) 181(47,0) 182(47.25,8.2) 183(47.5,0) 184(47.75,8.2) 185(48,0) 186(48.25,8.2) 187(48.5,0) 188(48.75,8.2) 189(49,0) 190(49.25,8.2) 191(49.5,0) 192(49.75,8.2) 193(50,0) 194(50.25,8.2) 195(50.5,0) 196(50.75,8.2) 197(51,0) 198(51.25,8.2) 199(51.5,0) 200(51.75,8.2) 201(52,0) 202(52.25,8.2) 203(52.5,0) 204(52.75,8.2) 205(53,0) 206(53.25,8.2) 207(53.5,0) 208(53.75,8.2) 209(54,0) 210(54.25,8.2) 211(54.5,0) 212(54.75,8.2) 213(55,0) 214(55.25,8.2) 215(55.5,0) 216(55.75,8.2) 217(56,0) 218(56.25,8.2) 219(56.5,0) 220(56.75,8.2) 221(57,0) 222(57.25,8.2) 223(57.5,0) 224(57.75,8.2) 225(58,0) 226(58.25,8.2) 227(58.5,0) 228(58.75,8.2) 229(59,0) 230(59.25,8.2) 231(59.5,0) 232(59.75,8.2) 233(60,0) 234(60.25,8.2) 235(60.5,0) 236(60.75,8.2) 237(61,0) 238(61.25,8.2) 239(61.5,0) 240(61.75,8.2) 241(62,0) 242(62.25,8.2) 243(62.5,0) 244(62.75,8.2) 245(63,0) 246(63.25,8.2) 247(63.5,0) 248(63.75,8.2) 249(64,0) 250(64.25,8.2) 251(64.5,0) 252(64.75,8.2) 253(65,0) 254(65.25,8.2) 255(65.5,0) 256(65.75,8.2) 257(66,0) 258(66.25,8.2) 259(66.5,0) 260(66.75,8.2)
  rect 3.505x4.597 smd: 261(-0.425,16.1) 262(67.175,16.1)
LOTES_ADDR0206-P001A02_260P
  round 1.092 hole 1.092 unplated: (-67.775,-4.1)
  round 1.6 hole 1.6 unplated: (1.025,-4.1)
  oval 0.305x1.753 smd: 1(0,0) 2(-0.25,-8.2) 3(-0.5,0) 4(-0.75,-8.2) 5(-1,0) 6(-1.25,-8.2) 7(-1.5,0) 8(-1.75,-8.2) 9(-2,0) 10(-2.25,-8.2) 11(-2.5,0) 12(-2.75,-8.2) 13(-3,0) 14(-3.25,-8.2) 15(-3.5,0) 16(-3.75,-8.2) 17(-4,0) 18(-4.25,-8.2) 19(-4.5,0) 20(-4.75,-8.2) 21(-5,0) 22(-5.25,-8.2) 23(-5.5,0) 24(-5.75,-8.2) 25(-6,0) 26(-6.25,-8.2) 27(-6.5,0) 28(-6.75,-8.2) 29(-7,0) 30(-7.25,-8.2) 31(-7.5,0) 32(-7.75,-8.2) 33(-8,0) 34(-8.25,-8.2) 35(-8.5,0) 36(-8.75,-8.2) 37(-9,0) 38(-9.25,-8.2) 39(-9.5,0) 40(-9.75,-8.2) 41(-10,0) 42(-10.25,-8.2) 43(-10.5,0) 44(-10.75,-8.2) 45(-11,0) 46(-11.25,-8.2) 47(-11.5,0) 48(-11.75,-8.2) 49(-12,0) 50(-12.25,-8.2) 51(-12.5,0) 52(-12.75,-8.2) 53(-13,0) 54(-13.25,-8.2) 55(-13.5,0) 56(-13.75,-8.2) 57(-14,0) 58(-14.25,-8.2) 59(-14.5,0) 60(-14.75,-8.2) 61(-15,0) 62(-15.25,-8.2) 63(-15.5,0) 64(-15.75,-8.2) 65(-16,0) 66(-16.25,-8.2) 67(-16.5,0) 68(-16.75,-8.2) 69(-17,0) 70(-17.25,-8.2) 71(-17.5,0) 72(-17.75,-8.2) 73(-18,0) 74(-18.25,-8.2) 75(-18.5,0) 76(-18.75,-8.2) 77(-19,0) 78(-19.25,-8.2) 79(-19.5,0) 80(-19.75,-8.2) 81(-20,0) 82(-20.25,-8.2) 83(-20.5,0) 84(-20.75,-8.2) 85(-21,0) 86(-21.25,-8.2) 87(-21.5,0) 88(-21.75,-8.2) 89(-22,0) 90(-22.25,-8.2) 91(-22.5,0) 92(-22.75,-8.2) 93(-23,0) 94(-23.25,-8.2) 95(-23.5,0) 96(-23.75,-8.2) 97(-24,0) 98(-24.25,-8.2) 99(-24.5,0) 100(-24.75,-8.2) 101(-25,0) 102(-25.25,-8.2) 103(-25.5,0) 104(-25.75,-8.2) 105(-26,0) 106(-26.25,-8.2) 107(-26.5,0) 108(-26.75,-8.2) 109(-27,0) 110(-27.25,-8.2) 111(-27.5,0) 112(-27.75,-8.2) 113(-28,0) 114(-28.25,-8.2) 115(-28.5,0) 116(-28.75,-8.2) 117(-29,0) 118(-29.25,-8.2) 119(-29.5,0) 120(-29.75,-8.2) 121(-30,0) 122(-30.25,-8.2) 123(-30.5,0) 124(-30.75,-8.2) 125(-31,0) 126(-31.25,-8.2) 127(-31.5,0) 128(-31.75,-8.2) 129(-32,0) 130(-32.25,-8.2) 131(-32.5,0) 132(-32.75,-8.2) 133(-33,0) 134(-33.25,-8.2) 135(-33.5,0) 136(-33.75,-8.2) 137(-34,0) 138(-34.25,-8.2) 139(-34.5,0) 140(-34.75,-8.2) 141(-35,0) 142(-35.25,-8.2) 143(-35.5,0) 144(-35.75,-8.2) 145(-38,0) 146(-38.25,-8.2) 147(-38.5,0) 148(-38.75,-8.2) 149(-39,0) 150(-39.25,-8.2) 151(-39.5,0) 152(-39.75,-8.2) 153(-40,0) 154(-40.25,-8.2) 155(-40.5,0) 156(-40.75,-8.2) 157(-41,0) 158(-41.25,-8.2) 159(-41.5,0) 160(-41.75,-8.2) 161(-42,0) 162(-42.25,-8.2) 163(-42.5,0) 164(-42.75,-8.2) 165(-43,0) 166(-43.25,-8.2) 167(-43.5,0) 168(-43.75,-8.2) 169(-44,0) 170(-44.25,-8.2) 171(-44.5,0) 172(-44.75,-8.2) 173(-45,0) 174(-45.25,-8.2) 175(-45.5,0) 176(-45.75,-8.2) 177(-46,0) 178(-46.25,-8.2) 179(-46.5,0) 180(-46.75,-8.2) 181(-47,0) 182(-47.25,-8.2) 183(-47.5,0) 184(-47.75,-8.2) 185(-48,0) 186(-48.25,-8.2) 187(-48.5,0) 188(-48.75,-8.2) 189(-49,0) 190(-49.25,-8.2) 191(-49.5,0) 192(-49.75,-8.2) 193(-50,0) 194(-50.25,-8.2) 195(-50.5,0) 196(-50.75,-8.2) 197(-51,0) 198(-51.25,-8.2) 199(-51.5,0) 200(-51.75,-8.2) 201(-52,0) 202(-52.25,-8.2) 203(-52.5,0) 204(-52.75,-8.2) 205(-53,0) 206(-53.25,-8.2) 207(-53.5,0) 208(-53.75,-8.2) 209(-54,0) 210(-54.25,-8.2) 211(-54.5,0) 212(-54.75,-8.2) 213(-55,0) 214(-55.25,-8.2) 215(-55.5,0) 216(-55.75,-8.2) 217(-56,0) 218(-56.25,-8.2) 219(-56.5,0) 220(-56.75,-8.2) 221(-57,0) 222(-57.25,-8.2) 223(-57.5,0) 224(-57.75,-8.2) 225(-58,0) 226(-58.25,-8.2) 227(-58.5,0) 228(-58.75,-8.2) 229(-59,0) 230(-59.25,-8.2) 231(-59.5,0) 232(-59.75,-8.2) 233(-60,0) 234(-60.25,-8.2) 235(-60.5,0) 236(-60.75,-8.2) 237(-61,0) 238(-61.25,-8.2) 239(-61.5,0) 240(-61.75,-8.2) 241(-62,0) 242(-62.25,-8.2) 243(-62.5,0) 244(-62.75,-8.2) 245(-63,0) 246(-63.25,-8.2) 247(-63.5,0) 248(-63.75,-8.2) 249(-64,0) 250(-64.25,-8.2) 251(-64.5,0) 252(-64.75,-8.2) 253(-65,0) 254(-65.25,-8.2) 255(-65.5,0) 256(-65.75,-8.2) 257(-66,0) 258(-66.25,-8.2) 259(-66.5,0) 260(-66.75,-8.2)
  rect 3.505x4.597 smd: 261(-67.175,7.9) 262(0.425,7.9)
LP2301ALT1G_SOT23-3
  oval 1.016x1.524 smd: 1(0,0) 2(0.965,2.083) 3(-0.965,2.083)
LRB715FT1G_SOT323-3
  oval 0.711x0.889 smd: 1(0,0) 2(0.65,1.9) 3(-0.65,1.9)
LTC015EUBFS8TL_UMT3F
  oval 0.787x0.889 smd: 1(0,0) 2(-0.65,-1.6) 3(0.65,-1.6)
MEC1416-NU-D0_VTQFP128_14X14
  oval 1.753x0.203 smd: 1(0,0) 2(0,-0.4) 3(0,-0.8) 4(0,-1.2) 5(0,-1.6) 6(0,-2) 7(0,-2.4) 8(0,-2.8) 9(0,-3.2) 10(0,-3.6) 11(0,-4) 12(0,-4.4) 13(0,-4.8) 14(0,-5.2) 15(0,-5.6) 16(0,-6) 17(0,-6.4) 18(0,-6.8) 19(0,-7.2) 20(0,-7.6) 21(0,-8) 22(0,-8.4) 23(0,-8.8) 24(0,-9.2) 25(0,-9.6) 26(0,-10) 27(0,-10.4) 28(0,-10.8) 29(0,-11.2) 30(0,-11.6) 31(0,-12) 32(0,-12.4) 65(15.654,-12.4) 66(15.654,-12) 67(15.654,-11.6) 68(15.654,-11.2) 69(15.654,-10.8) 70(15.654,-10.4) 71(15.654,-10) 72(15.654,-9.6) 73(15.654,-9.2) 74(15.654,-8.8) 75(15.654,-8.4) 76(15.654,-8) 77(15.654,-7.6) 78(15.654,-7.2) 79(15.654,-6.8) 80(15.654,-6.4) 81(15.654,-6) 82(15.654,-5.6) 83(15.654,-5.2) 84(15.654,-4.8) 85(15.654,-4.4) 86(15.654,-4) 87(15.654,-3.6) 88(15.654,-3.2) 89(15.654,-2.8) 90(15.654,-2.4) 91(15.654,-2) 92(15.654,-1.6) 93(15.654,-1.2) 94(15.654,-0.8) 95(15.654,-0.4) 96(15.654,0)
  oval 0.203x1.753 smd: 33(1.627,-14.027) 34(2.027,-14.027) 35(2.427,-14.027) 36(2.827,-14.027) 37(3.227,-14.027) 38(3.627,-14.027) 39(4.027,-14.027) 40(4.427,-14.027) 41(4.827,-14.027) 42(5.227,-14.027) 43(5.627,-14.027) 44(6.027,-14.027) 45(6.427,-14.027) 46(6.827,-14.027) 47(7.227,-14.027) 48(7.627,-14.027) 49(8.027,-14.027) 50(8.427,-14.027) 51(8.827,-14.027) 52(9.227,-14.027) 53(9.627,-14.027) 54(10.027,-14.027) 55(10.427,-14.027) 56(10.827,-14.027) 57(11.227,-14.027) 58(11.627,-14.027) 59(12.027,-14.027) 60(12.427,-14.027) 61(12.827,-14.027) 62(13.227,-14.027) 63(13.627,-14.027) 64(14.027,-14.027) 97(14.027,1.627) 98(13.627,1.627) 99(13.227,1.627) 100(12.827,1.627) 101(12.427,1.627) 102(12.027,1.627) 103(11.627,1.627) 104(11.227,1.627) 105(10.827,1.627) 106(10.427,1.627) 107(10.027,1.627) 108(9.627,1.627) 109(9.227,1.627) 110(8.827,1.627) 111(8.427,1.627) 112(8.027,1.627) 113(7.627,1.627) 114(7.227,1.627) 115(6.827,1.627) 116(6.427,1.627) 117(6.027,1.627) 118(5.627,1.627) 119(5.227,1.627) 120(4.827,1.627) 121(4.427,1.627) 122(4.027,1.627) 123(3.627,1.627) 124(3.227,1.627) 125(2.827,1.627) 126(2.427,1.627) 127(2.027,1.627) 128(1.627,1.627)
MMST3904-7-F_SOT323-3
  oval 0.711x0.889 smd: 1(0,0) 2(0.65,1.9) 3(-0.65,1.9)
MURAT_BLM15AG102SN1D_2P
  rect 0.457x0.508 smd: 1(0,0) 2(0.85,0)
MURAT_BLM15BD601SN1D_2P
  rect 0.508x0.762 smd: 1(0,0) 2(0.75,0)
MURAT_BLM15PD600SN1D_2P
  rect 0.508x0.762 smd: 1(0,0) 2(0.75,0)
MURAT_BLM15PX221SN1D_2P
  rect 0.457x0.508 smd: 1(0,0) 2(0.85,0)
MURAT_BLM15PX330SN1D_2P
  rect 0.457x0.508 smd: 1(0,0) 2(0.85,0)
NCP81218MNTXG_QFN48_6X6
  oval 0.889x0.203 smd: 1(0,0) 2(0,-0.4) 3(0,-0.8) 4(0,-1.2) 5(0,-1.6) 6(0,-2) 7(0,-2.4) 8(0,-2.8) 9(0,-3.2) 10(0,-3.6) 11(0,-4) 12(0,-4.4) 25(6.1,-4.4) 26(6.1,-4) 27(6.1,-3.6) 28(6.1,-3.2) 29(6.1,-2.8) 30(6.1,-2.4) 31(6.1,-2) 32(6.1,-1.6) 33(6.1,-1.2) 34(6.1,-0.8) 35(6.1,-0.4) 36(6.1,0)
  oval 0.203x0.889 smd: 13(0.85,-5.25) 14(1.25,-5.25) 15(1.65,-5.25) 16(2.05,-5.25) 17(2.45,-5.25) 18(2.85,-5.25) 19(3.25,-5.25) 20(3.65,-5.25) 21(4.05,-5.25) 22(4.45,-5.25) 23(4.85,-5.25) 24(5.25,-5.25) 37(5.25,0.85) 38(4.85,0.85) 39(4.45,0.85) 40(4.05,0.85) 41(3.65,0.85) 42(3.25,0.85) 43(2.85,0.85) 44(2.45,0.85) 45(2.05,0.85) 46(1.65,0.85) 47(1.25,0.85) 48(0.85,0.85)
  rect 4.496x4.496 smd: 49(3.05,-2.2)
NCP81253MNTBG_DFN8_2X2
  oval 0.254x0.787 smd: 1(0,0) 2(0.5,0) 3(1,0) 4(1.5,0) 5(1.5,2.2) 6(1,2.2) 7(0.5,2.2) 8(0,2.2)
  rect 1.194x0.787 smd: 9(0.75,1.1)
NCP302045MNTXG_PQFN33_5X5
  oval 0.305x0.711 smd: 1(0,-0.051) 2(0.5,-0.051) 3(1,-0.051) 4(1.5,-0.051) 5(2,-0.051) 6(2.5,-0.051) 7(3,-0.051) 8(3.5,-0.051)
  custom 0.32x0.32 smd: 9(3.135,1.215)
  custom 0.543x0.543 smd: 10(2.225,3.215)
  rect 3.81x0.711 smd: 11(1.75,4.851)
  rect 0.711x1.295 smd: 12(-0.701,3.65)
  oval 0.711x0.305 smd: 13(-0.701,2.65) 14(-0.701,2.15) 15(-0.701,1.65) 16(-0.701,1.15) 17(-0.701,0.65)
  rect 1.422x1.118 smd: 18(0.7,1.215)
  rect 0.584x0.356 smd: 19(0.09,2.625)
NCT7718W_MSOP8
  oval 0.381x1.575 smd: 1(0,0) 2(0.65,0) 3(1.3,0) 4(1.95,0) 5(1.95,4.35) 6(1.3,4.35) 7(0.65,4.35) 8(0,4.35)
NL17SZ06DFT2G_SC70-5
  oval 0.406x0.508 smd: 1(0,0) 2(0.65,0) 3(1.3,0) 4(1.3,1.9) 5(0,1.9)
NPCT650VB2YX_QFN32_5X5
  oval 0.889x0.254 smd: 1(0,0) 2(0,-0.5) 3(0,-1) 4(0,-1.5) 5(0,-2) 6(0,-2.5) 7(0,-3) 8(0,-3.5) 17(5.1,-3.5) 18(5.1,-3) 19(5.1,-2.5) 20(5.1,-2) 21(5.1,-1.5) 22(5.1,-1) 23(5.1,-0.5) 24(5.1,0)
  oval 0.254x0.889 smd: 9(0.8,-4.3) 10(1.3,-4.3) 11(1.8,-4.3) 12(2.3,-4.3) 13(2.8,-4.3) 14(3.3,-4.3) 15(3.8,-4.3) 16(4.3,-4.3) 25(4.3,0.8) 26(3.8,0.8) 27(3.3,0.8) 28(2.8,0.8) 29(2.3,0.8) 30(1.8,0.8) 31(1.3,0.8) 32(0.8,0.8)
  rect 3.505x3.505 smd: 33(2.55,-1.75)
R0402_0OHM
  rect 0.508x0.559 smd: 1(0,0) 2(0.914,0)
R0603_0OHM
  rect 0.635x0.889 smd: 1(0,0) 2(1.397,0)
R0805_0OHM
  rect 0.813x1.397 smd: 1(0,0) 2(1.702,0)
R_0402
  rect 0.508x0.559 smd: 1(0,0) 2(0.914,0)
R_0402-NPM
  rect 0.508x0.559 smd: 1(0,0) 2(0.914,0)
R_0603
  rect 0.635x0.889 smd: 1(0,0) 2(1.397,0)
R_0805
  rect 0.813x1.397 smd: 1(0,0) 2(1.702,0)
R_1206
  rect 1.016x1.651 smd: 1(0,0) 2(2.667,0)
R_1206_4P
  custom 0.476x0.476 smd: 1(0,0) 4(5.08,0)
  rect 1.397x0.381 smd: 2(1.206,0) 3(3.873,0)
RB551V-30_SOD323-2
  rect 0.559x0.813 smd: 1(0,0) 2(2.3,0)
RB751S40T1G_SOD523-2
  rect 0.61x0.787 smd: 1(0,0) 2(1.7,0)
RP_0804_8P4R
  oval 0.66x0.254 smd: 1(0,0) 2(0,-0.5) 3(0,-1) 4(0,-1.5) 5(1.15,-1.5) 6(1.15,-1) 7(1.15,-0.5) 8(1.15,0)
RT6226AGQUF_UQFN12_3X3
  oval 0.838x0.254 smd: 1(0,0) 6(3.15,0)
  oval 1.397x0.254 smd: 2(0.275,-0.72) 3(0.275,-1.62)
  oval 2.337x0.254 smd: 4(2.41,-1.17) 5(2.41,-0.45)
  oval 0.254x0.838 smd: 7(2.7,0.955) 8(2.25,0.955) 9(1.8,0.955) 10(1.35,0.955) 11(0.9,0.955) 12(0.45,0.955)
RT8061AZQW_WDFN10_3X3
  oval 0.254x0.889 smd: 1(0,0) 2(0.5,0) 3(1,0) 4(1.5,0) 5(2,0) 6(2,3.1) 7(1.5,3.1) 8(1,3.1) 9(0.5,3.1) 10(0,3.1)
  rect 2.464x1.626 smd: 11(1,1.55)
RT8207PGQW_WQFN20_3X3
  oval 0.203x0.889 smd: 1(0,0) 2(0.4,0) 3(0.8,0) 4(1.2,0) 5(1.6,0) 11(1.6,3.1) 12(1.2,3.1) 13(0.8,3.1) 14(0.4,3.1) 15(0,3.1)
  oval 0.889x0.203 smd: 6(2.35,0.75) 7(2.35,1.15) 8(2.35,1.55) 9(2.35,1.95) 10(2.35,2.35) 16(-0.75,2.35) 17(-0.75,1.95) 18(-0.75,1.55) 19(-0.75,1.15) 20(-0.75,0.75)
  rect 1.702x1.702 smd: 21(0.8,1.55)
RT9059GSP_SO8
  oval 0.635x1.854 smd: 1(0,0) 2(1.27,0) 3(2.54,0) 4(3.81,0) 5(3.81,5.157) 6(2.54,5.157) 7(1.27,5.157) 8(0,5.157)
  rect 2.311x2.311 smd: 9(1.905,2.579)
RTL8106E-CG_QFN32_4X4-S
  oval 0.203x0.838 smd: 1(0,0) 2(0.4,0) 3(0.8,0) 4(1.2,0) 5(1.6,0) 6(2,0) 7(2.4,0) 8(2.8,0) 17(2.8,4.15) 18(2.4,4.15) 19(2,4.15) 20(1.6,4.15) 21(1.2,4.15) 22(0.8,4.15) 23(0.4,4.15) 24(0,4.15)
  oval 0.838x0.203 smd: 9(3.475,0.675) 10(3.475,1.075) 11(3.475,1.475) 12(3.475,1.875) 13(3.475,2.275) 14(3.475,2.675) 15(3.475,3.075) 16(3.475,3.475) 25(-0.675,3.475) 26(-0.675,3.075) 27(-0.675,2.675) 28(-0.675,2.275) 29(-0.675,1.875) 30(-0.675,1.475) 31(-0.675,1.075) 32(-0.675,0.675)
  rect 2.692x2.692 smd: 33(1.4,2.075)
RUM002N02GT2L_VMT3
  oval 0.508x0.457 smd: 1(0,0)
  oval 0.406x0.457 smd: 2(-0.4,-1.15) 3(0.4,-1.15)
SDMK0340L-7-F_SOD323-2
  rect 1.346x0.66 smd: 1(0,0) 2(2.4,0)
SHORTPADS
  custom 0.19x0.19 smd: 1(-0.483,0) 2(0.483,0)
SI2301CDS-T1-GE3_SOT23-3
  oval 1.016x1.524 smd: 1(0,0) 2(0.965,2.083) 3(-0.965,2.083)
SINGA_2RJ3076-078211F_8P-T
  round 1.295 hole 0.889: 1(0,0) 2(-1.02,1.1) 3(-2.04,0) 4(-3.06,1.1) 5(-4.08,0) 6(-5.1,1.1) 7(-6.12,0) 8(-7.14,1.1)
  oval 0.991x2.007 hole 0.61x1.6: 9(4.83,-2.3) 10(4.83,-10.1) 11(-11.97,-10.1) 12(-11.97,-2.3)
SKL-U_BGA_1356P-T
  round 0.356 smd: A3(-0.965,0) A70(-40.166,0) B2(-0.483,0.483) B71(-40.629,0.462) BA1(0,22.166) BA71(-40.629,22.166) BB2(-0.462,22.628) BB70(-40.166,22.628) C1(0,0.965)
  round 0.33 smd: A4(-1.615,0) A69(-39.516,0) AY1(0,21.516) AY71(-40.629,21.516) B3(-1.118,0.635) B70(-39.999,0.63) BA2(-0.629,21.999) BA70(-39.999,21.999) BB3(-1.113,22.628) BB69(-39.516,22.628) C2(-0.635,1.118) C71(-40.629,1.113) D1(0,1.615)
  round 0.305 smd: A5(-2.266,0) A68(-38.866,0) AA2(-0.975,10.804) AA4(-1.951,10.804) AA63(-35.427,10.719) AA64(-36.077,10.719) AA65(-36.727,10.719) AA66(-37.377,10.719) AA67(-38.028,10.719) AA68(-38.678,10.719) AA69(-39.328,10.719) AA70(-39.978,10.719) AA71(-40.629,10.719) AB4(-1.951,11.467) AB6(-2.729,11.181) AB7(-3.379,11.181) AB8(-4.029,11.181) AB9(-4.679,11.181) AB10(-5.33,11.181) AB11(-5.98,11.181) AB12(-6.63,11.181) AB13(-7.28,11.181) AB15(-8.126,11.305) AB16(-8.776,11.305) AB17(-9.426,11.305) AB18(-10.077,11.305) AB19(-10.727,11.305) AB20(-11.377,11.305) AB21(-12.027,11.305) AB62(-34.958,11.176) AC3(-1.626,12.13) AC63(-35.427,11.633) AC64(-36.077,11.633) AC65(-36.727,11.633) AC66(-37.377,11.633) AC67(-38.028,11.633) AC68(-38.678,11.633) AC69(-39.328,11.633) AC70(-39.978,11.633) AC71(-40.629,11.633) AD4(-1.951,12.792) AD6(-2.729,12.248) AD7(-3.379,12.248) AD8(-4.029,12.248) AD9(-4.679,12.248) AD10(-5.33,12.248) AD11(-5.98,12.248) AD12(-6.63,12.248) AD13(-7.28,12.248) AD15(-8.126,12.143) AD16(-8.776,12.143) AD17(-9.426,12.143) AD18(-10.077,12.143) AD19(-10.727,12.143) AD20(-11.377,12.143) AD21(-12.027,12.143) AD62(-34.958,12.09) AE62(-34.958,13.005) AE63(-35.427,12.547) AE64(-36.077,12.547) AE65(-36.727,12.547) AE66(-37.377,12.547) AE67(-38.028,12.547) AE68(-38.678,12.547) AE69(-39.328,12.547) AF2(-0.975,13.455) AF4(-1.951,13.455) AF6(-2.729,13.315) AF7(-3.379,13.315) AF8(-4.029,13.315) AF9(-4.679,13.315) AF10(-5.33,13.315) AF11(-5.98,13.315) AF12(-6.63,13.315) AF13(-7.28,13.315) AF15(-8.126,12.982) AF16(-8.776,12.982) AF17(-9.426,12.982) AF18(-10.077,12.982) AF19(-10.727,12.982) AF20(-11.377,12.982) AF21(-12.027,12.982) AF63(-35.427,13.462) AF64(-36.077,13.462) AF65(-36.727,13.462) AF66(-37.377,13.462) AF67(-38.028,13.462) AF68(-38.678,13.253) AF69(-39.328,13.253) AG4(-1.951,14.118) AG15(-8.126,13.82) AG16(-8.776,13.82) AG17(-9.426,13.82) AG18(-10.077,13.82) AG19(-10.727,13.82) AG20(-11.377,13.82) AG21(-12.027,13.82) AG62(-34.958,13.919) AG69(-39.003,13.916) AH3(-1.626,14.781) AH6(-2.729,14.381) AH7(-3.379,14.381) AH8(-4.029,14.381) AH9(-4.679,14.381) AH10(-5.33,14.381) AH11(-5.98,14.381) AH12(-6.63,14.381) AH13(-7.28,14.381) AH63(-35.427,14.376) AH64(-36.077,14.376) AH65(-36.727,14.376) AH66(-37.377,14.376) AH67(-38.028,14.376) AJ4(-1.951,15.444) AJ15(-8.126,14.658) AJ16(-8.776,14.658) AJ17(-9.426,14.658) AJ18(-10.077,14.658) AJ19(-10.727,14.658) AJ20(-11.377,14.658) AJ21(-12.027,14.658) AJ62(-34.958,14.833) AK6(-2.729,15.321) AK7(-3.379,15.321) AK8(-4.029,15.321) AK9(-4.679,15.321) AK10(-5.33,15.321) AK11(-5.98,15.321) AK12(-6.63,15.321) AK13(-7.28,15.321) AK15(-8.126,15.496) AK16(-8.776,15.496) AK17(-9.426,15.496) AK18(-10.077,15.496) AK19(-10.727,15.496) AK20(-11.377,15.496) AK21(-12.027,15.496) AK22(-12.719,15.323) AK23(-13.633,15.323) AK25(-14.547,15.323) AK27(-15.462,15.323) AK28(-16.376,15.323) AK30(-17.291,15.323) AK32(-18.205,15.323) AK33(-19.119,15.323) AK35(-20.034,15.323) AK37(-20.948,15.323) AK38(-21.863,15.323) AK40(-22.777,15.323) AK42(-23.691,15.323) AK43(-24.606,15.323) AK45(-25.52,15.323) AK46(-26.435,15.323) AK48(-27.349,15.323) AK50(-28.263,15.323) AK52(-29.178,15.323) AK53(-30.092,15.323) AK55(-31.007,15.323) AK56(-31.921,15.323) AK58(-32.835,15.323) AK60(-33.75,15.323) AK62(-34.774,15.458) AK63(-35.427,15.291) AK64(-36.077,15.291) AK65(-36.727,15.291) AK66(-37.377,15.291) AK67(-38.028,15.291) AK68(-38.678,15.143) AK69(-39.653,15.143) AL2(-0.975,16.107) AL4(-1.951,16.107) AL23(-13.176,15.788) AL25(-14.09,15.788) AL27(-15.005,15.788) AL28(-15.919,15.788) AL30(-16.833,15.788) AL32(-17.748,15.788) AL33(-18.662,15.788) AL35(-19.577,15.788) AL37(-20.491,15.788) AL38(-21.405,15.788) AL40(-22.32,15.788) AL42(-23.234,15.788) AL43(-24.149,15.788) AL45(-25.063,15.788) AL46(-25.977,15.788) AL48(-26.892,15.788) AL50(-27.806,15.788) AL52(-28.721,15.788) AL53(-29.635,15.788) AL55(-30.549,15.788) AL56(-31.464,15.788) AL58(-32.378,15.788) AL60(-33.293,15.788) AL61(-34.207,15.788) AL63(-35.427,16.159) AL64(-36.077,16.159) AL65(-36.727,16.159) AL66(-37.377,16.159) AM4(-1.951,16.77) AM5(-2.66,16.261) AM7(-3.575,16.261) AM8(-4.489,16.261) AM10(-5.403,16.261) AM11(-6.318,16.261) AM13(-7.232,16.261) AM15(-8.147,16.261) AM16(-9.061,16.261) AM18(-9.975,16.261) AM20(-10.89,16.261) AM21(-11.804,16.261) AM22(-12.719,16.261) AM23(-13.633,16.261) AM25(-14.547,16.261) AM27(-15.462,16.261) AM28(-16.376,16.261) AM30(-17.291,16.261) AM32(-18.205,16.261) AM33(-19.119,16.261) AM35(-20.034,16.261) AM37(-20.948,16.261) AM38(-21.863,16.261) AM40(-22.777,16.261) AM42(-23.691,16.261) AM43(-24.606,16.261) AM45(-25.52,16.261) AM46(-26.435,16.261) AM48(-27.349,16.261) AM50(-28.263,16.261) AM52(-29.178,16.261) AM53(-30.092,16.261) AM55(-31.007,16.261) AM56(-31.921,16.261) AM58(-32.835,16.261) AM60(-33.75,16.261) AM61(-34.664,16.261) AM68(-38.353,16.37) AM69(-39.003,16.37) AN3(-1.626,17.433) AN5(-2.66,16.911) AN7(-3.575,16.911) AN8(-4.489,16.911) AN10(-5.403,16.911) AN11(-6.318,16.911) AN13(-7.232,16.911) AN15(-8.147,16.911) AN16(-9.061,16.911) AN18(-9.975,16.911) AN20(-10.89,16.911) AN21(-11.804,16.911) AN22(-12.719,16.911) AN23(-13.633,16.911) AN25(-14.547,16.911) AN27(-15.462,16.911) AN28(-16.376,16.911) AN30(-17.291,16.911) AN32(-18.205,16.911) AN33(-19.119,16.911) AN35(-20.034,16.911) AN37(-20.948,16.911) AN38(-21.863,16.911) AN40(-22.777,16.911) AN42(-23.691,16.911) AN43(-24.606,16.911) AN45(-25.52,16.911) AN46(-26.435,16.911) AN48(-27.349,16.911) AN50(-28.263,16.911) AN52(-29.178,16.911) AN53(-30.092,16.911) AN55(-31.007,16.911) AN56(-31.921,16.911) AN58(-32.835,16.911) AN60(-33.75,16.911) AN61(-34.664,16.911) AN63(-35.579,16.911) AN65(-36.493,16.911) AN66(-37.407,16.911) AN68(-38.678,17.033) AN69(-39.328,17.033) AP4(-1.951,18.096) AP5(-2.66,17.561) AP7(-3.575,17.561) AP8(-4.489,17.561) AP10(-5.403,17.561) AP11(-6.318,17.561) AP13(-7.232,17.561) AP15(-8.147,17.561) AP16(-9.061,17.561) AP18(-9.975,17.561) AP20(-10.89,17.561) AP21(-11.804,17.561) AP22(-12.719,17.561) AP23(-13.633,17.561) AP25(-14.547,17.561) AP27(-15.462,17.561) AP28(-16.376,17.561) AP30(-17.291,17.561) AP32(-18.205,17.561) AP33(-19.119,17.561) AP35(-20.034,17.561) AP37(-20.948,17.561) AP38(-21.863,17.561) AP40(-22.777,17.561) AP42(-23.691,17.561) AP43(-24.606,17.561) AP45(-25.52,17.561) AP46(-26.435,17.561) AP48(-27.349,17.561) AP50(-28.263,17.561) AP52(-29.178,17.561) AP53(-30.092,17.561) AP55(-31.007,17.561) AP56(-31.921,17.561) AP58(-32.835,17.561) AP60(-33.75,17.561) AP61(-34.664,17.561) AP63(-35.579,17.561) AP65(-36.493,17.561) AP66(-37.407,17.561) AP68(-38.353,17.646) AP70(-39.572,17.646) AR5(-2.66,18.211) AR7(-3.575,18.211) AR8(-4.489,18.211) AR10(-5.403,18.211) AR11(-6.318,18.211) AR13(-7.232,18.211) AR15(-8.147,18.211) AR16(-9.061,18.211) AR18(-9.975,18.211) AR20(-10.89,18.211) AR21(-11.804,18.211) AR22(-12.719,18.211) AR23(-13.633,18.211) AR25(-14.547,18.211) AR27(-15.462,18.211) AR28(-16.376,18.211) AR30(-17.291,18.211) AR32(-18.205,18.211) AR33(-19.119,18.211) AR35(-20.034,18.211) AR37(-20.948,18.211) AR38(-21.863,18.211) AR40(-22.777,18.211) AR42(-23.691,18.211) AR43(-24.606,18.211) AR45(-25.52,18.211) AR46(-26.435,18.211) AR48(-27.349,18.211) AR50(-28.263,18.211) AR52(-29.178,18.211) AR53(-30.092,18.211) AR55(-31.007,18.211) AR56(-31.921,18.211) AR58(-32.835,18.211) AR60(-33.75,18.211) AR61(-34.664,18.211) AR63(-35.579,18.211) AR65(-36.493,18.211) AR66(-37.407,18.211) AR68(-38.678,18.26) AR69(-39.328,18.26) AT2(-0.975,18.759) AT4(-1.951,18.759) AT5(-2.66,18.862) AT7(-3.575,18.862) AT8(-4.489,18.862) AT10(-5.403,18.862) AT11(-6.318,18.862) AT13(-7.232,18.862) AT15(-8.147,18.862) AT16(-9.061,18.862) AT18(-9.975,18.862) AT20(-10.89,18.862) AT21(-11.804,18.862) AT22(-12.719,18.862) AT23(-13.633,18.862) AT25(-14.547,18.862) AT27(-15.462,18.862) AT28(-16.376,18.862) AT30(-17.291,18.862) AT32(-18.205,18.862) AT33(-19.119,18.862) AT35(-20.034,18.862) AT37(-20.948,18.862) AT38(-21.863,18.862) AT40(-22.777,18.862) AT42(-23.691,18.862) AT43(-24.606,18.862) AT45(-25.52,18.862) AT46(-26.435,18.862) AT48(-27.349,18.862) AT50(-28.263,18.862) AT52(-29.178,18.862) AT53(-30.092,18.862) AT55(-31.007,18.862) AT56(-31.921,18.862) AT58(-32.835,18.862) AT60(-33.75,18.862) AT61(-34.664,18.862) AT63(-35.579,18.862) AT65(-36.493,18.862) AT66(-37.407,18.862) AT68(-38.353,18.823) AT69(-39.003,18.823) AU4(-1.951,19.422) AU5(-2.66,19.512) AU7(-3.575,19.512) AU8(-4.489,19.512) AU10(-5.403,19.512) AU11(-6.318,19.512) AU13(-7.232,19.512) AU15(-8.147,19.512) AU16(-9.061,19.512) AU18(-9.975,19.512) AU20(-10.89,19.512) AU21(-11.804,19.512) AU22(-12.719,19.512) AU23(-13.633,19.512) AU25(-14.547,19.512) AU27(-15.462,19.512) AU28(-16.376,19.512) AU30(-17.291,19.512) AU32(-18.205,19.512) AU33(-19.119,19.512) AU35(-20.034,19.512) AU37(-20.948,19.512) AU38(-21.863,19.512) AU40(-22.777,19.512) AU42(-23.691,19.512) AU43(-24.606,19.512) AU45(-25.52,19.512) AU46(-26.435,19.512) AU48(-27.349,19.512) AU50(-28.263,19.512) AU52(-29.178,19.512) AU53(-30.092,19.512) AU55(-31.007,19.512) AU56(-31.921,19.512) AU58(-32.835,19.512) AU60(-33.75,19.512) AU61(-34.664,19.512) AU63(-35.579,19.512) AU65(-36.493,19.512) AU66(-37.407,19.512) AV3(-1.626,20.113) AV68(-38.343,20.026) AV69(-39.328,20.215) AV70(-39.978,20.215) AW1(0,20.866) AW5(-2.534,20.226) AW6(-3.184,20.353) AW7(-3.75,20.678) AW8(-4.328,20.353) AW9(-4.898,20.678) AW10(-5.561,20.353) AW11(-6.171,20.678) AW12(-6.749,20.353) AW13(-7.319,20.678) AW14(-7.982,20.353) AW15(-8.592,20.678) AW16(-9.17,20.353) AW17(-9.74,20.678) AW18(-10.403,20.353) AW20(-11.012,20.678) AW21(-11.59,20.353) AW22(-12.16,20.678) AW23(-12.849,20.353) AW25(-13.486,20.678) AW26(-14.05,20.353) AW27(-14.713,20.678) AW28(-15.326,20.353) AW29(-15.94,20.678) AW30(-16.603,20.353) AW31(-17.167,20.678) AW32(-17.83,20.353) AW33(-18.467,20.678) AW34(-19.031,20.353) AW35(-19.694,20.678) AW36(-20.307,20.353) AW37(-20.921,20.678) AW38(-21.584,20.353) AW39(-22.148,20.678) AW41(-22.785,20.353) AW42(-23.423,20.678) AW43(-23.986,20.353) AW44(-24.649,20.678) AW45(-25.263,20.353) AW46(-25.876,20.678) AW47(-26.477,20.353) AW48(-27.041,20.678) AW49(-27.669,20.353) AW50(-28.298,20.678) AW51(-28.862,20.353) AW52(-29.463,20.678) AW53(-30.076,20.353) AW54(-30.69,20.678) AW55(-31.352,20.353) AW56(-31.916,20.678) AW57(-32.554,20.353) AW59(-33.191,20.678) AW60(-33.755,20.353) AW61(-34.418,20.678) AW62(-35.032,20.353) AW63(-35.645,20.678) AW64(-36.308,20.353) AW65(-36.872,20.678) AW66(-37.407,20.215) AW67(-38.332,20.685) AW68(-38.936,20.936) AW69(-39.581,20.85) AW70(-39.999,21.349) AW71(-40.629,20.866) AY2(-0.629,21.348) AY3(-1.286,21.342) AY4(-2.04,21.357) AY5(-2.649,21.003) AY8(-4.328,21.003) AY12(-6.749,21.003) AY16(-9.17,21.003) AY21(-11.59,21.003) AY26(-14.05,21.003) AY27(-14.713,21.328) AY29(-15.94,21.328) AY30(-16.603,21.003) AY34(-19.031,21.003) AY35(-19.694,21.328) AY37(-20.921,21.328) AY38(-21.584,21.003) AY43(-23.986,21.003) AY44(-24.649,21.328) AY46(-25.876,21.328) AY47(-26.477,21.003) AY51(-28.862,21.003) AY52(-29.463,21.328) AY54(-30.69,21.328) AY55(-31.352,21.003) AY60(-33.755,21.003) AY61(-34.418,21.328) AY63(-35.645,21.328) AY64(-36.308,21.003) AY66(-37.535,21.003) AY68(-38.85,21.581) B5(-2.266,0.65) B6(-2.847,0.975) B10(-5.325,0.975) B14(-7.803,0.975) B18(-10.281,0.975) B22(-12.759,0.975) B26(-15.237,0.975) B30(-17.715,0.975) B34(-20.194,0.975) B39(-22.672,0.975) B44(-25.15,0.975) B48(-27.628,0.975) B53(-30.106,0.975) B58(-32.584,0.975) B62(-35.062,0.975) B66(-37.54,0.975) B69(-39.349,0.63) BA3(-1.279,21.999) BA5(-2.599,21.94) BA8(-4.328,21.653) BA12(-6.749,21.653) BA16(-9.17,21.653) BA21(-11.59,21.653) BA23(-12.849,21.572) BA28(-15.326,21.572) BA32(-17.83,21.572) BA36(-20.307,21.572) BA41(-22.785,21.572) BA45(-25.263,21.572) BA49(-27.669,21.653) BA53(-30.076,21.572) BA57(-32.554,21.572) BA62(-35.032,21.572) BA68(-39.349,21.999) BB4(-1.763,22.628) BB68(-38.866,22.628) C4(-1.699,0.978) C5(-2.266,1.3) C7(-3.523,1.3) C8(-4.086,0.975) C9(-4.65,1.3) C11(-6.001,1.3) C12(-6.564,0.975) C13(-7.128,1.3) C15(-8.479,1.3) C16(-9.042,0.975) C17(-9.606,1.3) C19(-10.957,1.3) C20(-11.52,0.975) C21(-12.084,1.3) C23(-13.435,1.3) C24(-13.998,0.975) C25(-14.562,1.3) C27(-15.913,1.3) C28(-16.476,0.975) C29(-17.04,1.3) C31(-18.391,1.3) C32(-18.954,0.975) C33(-19.518,1.3) C36(-20.869,1.3) C37(-21.433,0.975) C38(-21.996,1.3) C40(-23.347,1.3) C41(-23.911,0.975) C42(-24.474,1.3) C45(-25.825,1.3) C46(-26.389,0.975) C47(-26.952,1.3) C50(-28.303,1.3) C51(-28.867,0.975) C52(-29.43,1.3) C54(-30.781,1.3) C55(-31.345,0.975) C56(-31.908,1.3) C59(-33.259,1.3) C60(-33.823,0.975) C61(-34.386,1.3) C63(-35.737,1.3) C64(-36.301,0.975) C65(-36.864,1.3) C67(-38.799,1.015) C68(-38.936,1.693) C70(-39.999,1.28) D3(-0.975,1.706) D4(-1.624,1.646) D5(-2.224,1.951) D6(-2.873,1.991) D7(-3.523,1.951) D8(-4.086,1.626) D9(-4.65,1.951) D10(-5.325,1.991) D11(-6.001,1.951) D12(-6.564,1.626) D13(-7.128,1.951) D14(-7.803,1.991) D15(-8.479,1.951) D16(-9.042,1.626) D17(-9.606,1.951) D18(-10.281,1.991) D19(-10.957,1.951) D20(-11.52,1.626) D21(-12.084,1.951) D22(-12.759,1.991) D23(-13.435,1.951) D24(-13.998,1.626) D25(-14.562,1.951) D26(-15.237,1.991) D27(-15.913,1.951) D28(-16.476,1.626) D29(-17.04,1.951) D30(-17.715,1.991) D31(-18.391,1.951) D32(-18.954,1.626) D33(-19.518,1.951) D34(-20.194,1.991) D36(-20.869,1.951) D37(-21.433,1.626) D38(-21.996,1.951) D39(-22.672,1.991) D40(-23.347,1.951) D41(-23.911,1.626) D42(-24.474,1.951) D44(-25.15,1.991) D45(-25.825,1.951) D46(-26.389,1.626) D47(-26.952,1.951) D48(-27.628,1.991) D50(-28.303,1.951) D51(-28.867,1.626) D52(-29.43,1.951) D53(-30.106,1.991) D54(-30.781,1.951) D55(-31.345,1.626) D56(-31.908,1.951) D58(-32.584,1.991) D59(-33.259,1.951) D60(-33.823,1.626) D61(-34.386,1.951) D62(-35.062,1.991) D63(-35.737,1.951) D64(-36.301,1.626) D65(-36.864,1.951) D66(-37.54,1.991) D67(-38.213,1.3) D68(-39.582,1.779) D69(-38.876,2.343) D71(-40.629,1.763) E1(0,2.274) E2(-0.65,2.274) E3(-1.3,2.274) E5(-2.66,2.723) E6(-3.575,2.723) E8(-4.489,2.723) E10(-5.403,2.723) E11(-6.318,2.723) E13(-7.232,2.723) E15(-8.147,2.723) E16(-9.061,2.723) E18(-9.975,2.723) E20(-10.89,2.723) E21(-11.804,2.723) E22(-12.719,2.723) E23(-13.633,2.723) E25(-14.547,2.723) E27(-15.462,2.723) E28(-16.376,2.723) E30(-17.291,2.723) E32(-18.205,2.723) E33(-19.119,2.723) E35(-20.034,2.723) E37(-20.948,2.723) E38(-21.863,2.723) E40(-22.777,2.723) E42(-23.691,2.723) E43(-24.606,2.723) E45(-25.52,2.723) E46(-26.435,2.723) E48(-27.349,2.723) E50(-28.263,2.723) E52(-29.178,2.723) E53(-30.092,2.723) E55(-31.007,2.723) E56(-31.921,2.723) E58(-32.835,2.723) E60(-33.75,2.723) E61(-34.664,2.723) E63(-35.629,2.659) E65(-36.645,2.659) E66(-37.661,2.659) E68(-38.213,1.951) F2(-0.975,2.848) F4(-1.951,2.848) F5(-2.66,3.373) F6(-3.575,3.373) F8(-4.489,3.373) F10(-5.403,3.373) F11(-6.318,3.373) F13(-7.232,3.373) F15(-8.147,3.373) F16(-9.061,3.373) F18(-9.975,3.373) F20(-10.89,3.373) F21(-11.804,3.373) F22(-12.719,3.373) F23(-13.633,3.373) F25(-14.547,3.373) F27(-15.462,3.373) F28(-16.376,3.373) F30(-17.291,3.373) F32(-18.205,3.373) F33(-19.119,3.373) F35(-20.034,3.373) F37(-20.948,3.373) F38(-21.863,3.373) F40(-22.777,3.373) F42(-23.691,3.373) F43(-24.606,3.373) F45(-25.52,3.373) F46(-26.435,3.373) F48(-27.349,3.373) F50(-28.263,3.373) F52(-29.178,3.373) F53(-30.092,3.373) F55(-31.007,3.373) F56(-31.921,3.373) F58(-32.835,3.373) F60(-33.75,3.373) F61(-34.664,3.373) F63(-35.629,3.31) F65(-36.645,3.31) F66(-37.661,3.31) F68(-38.876,2.994) G4(-1.951,3.511) G5(-2.66,4.023) G6(-3.575,4.023) G8(-4.489,4.023) G10(-5.403,4.023) G11(-6.318,4.023) G13(-7.232,4.023) G15(-8.147,4.023) G16(-9.061,4.023) G18(-9.975,4.023) G20(-10.89,4.023) G21(-11.804,4.023) G22(-12.719,4.023) G23(-13.633,4.023) G25(-14.547,4.023) G27(-15.462,4.023) G28(-16.376,4.023) G30(-17.291,4.023) G32(-18.205,4.023) G33(-19.119,4.023) G35(-20.034,4.023) G37(-20.948,4.023) G38(-21.863,4.023) G40(-22.777,4.023) G42(-23.691,4.023) G43(-24.606,4.023) G45(-25.52,4.023) G46(-26.435,4.023) G48(-27.349,4.023) G50(-28.263,4.023) G52(-29.178,4.023) G53(-30.092,4.023) G55(-31.007,4.023) G56(-31.921,4.023) G58(-32.835,4.023) G60(-33.75,4.023) G61(-34.664,4.023) G63(-35.629,3.96) G65(-36.645,3.96) G66(-37.661,3.96) G68(-38.678,3.655) G69(-39.328,3.655) H3(-1.626,4.174) H5(-2.66,4.674) H6(-3.575,4.674) H8(-4.489,4.674) H10(-5.403,4.674) H11(-6.318,4.674) H13(-7.232,4.674) H15(-8.147,4.674) H16(-9.061,4.674) H18(-9.975,4.674) H20(-10.89,4.674) H21(-11.804,4.674) H63(-35.629,4.61) H65(-36.645,4.61) H66(-37.661,4.61) H69(-39.003,4.218) J4(-1.951,4.837) J5(-2.66,5.324) J6(-3.575,5.324) J8(-4.489,5.324) J10(-5.403,5.324) J11(-6.318,5.324) J13(-7.232,5.324) J22(-13.176,4.488) J23(-14.09,4.488) J25(-15.005,4.488) J27(-15.919,4.488) J28(-16.833,4.488) J30(-17.748,4.488) J32(-18.662,4.488) J33(-19.577,4.488) J35(-20.491,4.488) J37(-21.405,4.488) J38(-22.32,4.488) J40(-23.234,4.488) J42(-24.149,4.488) J43(-25.063,4.488) J45(-25.977,4.488) J46(-26.892,4.488) J48(-27.806,4.488) J50(-28.721,4.488) J52(-29.635,4.488) J53(-30.549,4.488) J55(-31.464,4.488) J56(-32.378,4.488) J58(-33.293,4.488) J60(-34.207,4.488) J68(-38.676,4.794) K15(-8.126,5.438) K16(-8.776,5.438) K17(-9.426,5.438) K18(-10.077,5.438) K19(-10.727,5.438) K20(-11.377,5.438) K21(-12.027,5.438) K22(-12.719,4.952) K23(-13.633,4.952) K25(-14.547,4.952) K27(-15.462,4.952) K28(-16.376,4.952) K30(-17.291,4.952) K32(-18.205,4.952) K33(-19.119,4.952) K35(-20.034,4.952) K37(-20.948,4.952) K38(-21.863,4.952) K40(-22.777,4.952) K42(-23.691,4.952) K43(-24.606,4.952) K45(-25.52,4.952) K46(-26.435,4.952) K48(-27.349,4.952) K50(-28.263,4.952) K52(-29.178,4.952) K53(-30.092,4.952) K55(-31.007,4.952) K56(-31.921,4.952) K58(-32.835,4.952) K60(-33.75,4.952) K61(-34.664,4.952) K63(-35.447,5.26) K64(-36.097,5.26) K65(-36.747,5.26) K66(-37.398,5.26) K67(-38.048,5.26) K68(-38.666,5.468) K70(-39.653,5.57) L2(-0.975,5.5) L4(-1.951,5.5) L6(-2.729,5.974) L7(-3.379,5.974) L8(-4.029,5.974) L9(-4.679,5.974) L10(-5.33,5.974) L11(-5.98,5.974) L12(-6.63,5.974) L13(-7.28,5.974) L15(-8.126,6.276) L16(-8.776,6.276) L17(-9.426,6.276) L18(-10.077,6.276) L19(-10.727,6.276) L20(-11.377,6.276) L21(-12.027,6.276) L62(-34.958,5.689) L63(-35.427,6.147) L64(-36.077,6.147) L65(-36.727,6.147) L66(-37.377,6.147) L67(-38.028,6.147) L68(-38.678,6.147) L69(-39.328,6.147) L70(-39.978,6.147) L71(-40.629,6.147) M4(-1.951,6.163) M62(-34.958,6.604) N3(-1.626,6.826) N6(-2.729,6.914) N7(-3.379,6.914) N8(-4.029,6.914) N9(-4.679,6.914) N10(-5.33,6.914) N11(-5.98,6.914) N12(-6.63,6.914) N13(-7.28,6.914) N15(-8.126,7.114) N16(-8.776,7.114) N17(-9.426,7.114) N18(-10.077,7.114) N19(-10.727,7.114) N20(-11.377,7.114) N21(-12.027,7.114) N63(-35.427,7.061) N64(-36.077,7.061) N65(-36.727,7.061) N66(-37.377,7.061) N67(-38.028,7.061) N68(-38.678,7.061) N69(-39.328,7.061) N70(-39.978,7.061) N71(-40.629,7.061) P4(-1.951,7.489) P15(-8.126,7.952) P16(-8.776,7.952) P17(-9.426,7.952) P18(-10.077,7.952) P19(-10.727,7.952) P20(-11.377,7.952) P21(-12.027,7.952) P62(-34.958,7.518) R6(-2.729,7.981) R7(-3.379,7.981) R8(-4.029,7.981) R9(-4.679,7.981) R10(-5.33,7.981) R11(-5.98,7.981) R12(-6.63,7.981) R13(-7.28,7.981) R63(-35.427,7.975) R64(-36.077,7.975) R65(-36.727,7.975) R66(-37.377,7.975) R67(-38.028,7.975) R68(-38.678,7.975) R69(-39.328,7.975) R70(-39.978,7.975) R71(-40.629,7.975) T2(-0.975,8.152) T4(-1.951,8.152) T15(-8.126,8.791) T16(-8.776,8.791) T17(-9.426,8.791) T18(-10.077,8.791) T19(-10.727,8.791) T20(-11.377,8.791) T21(-12.027,8.791) T62(-34.958,8.433) U4(-1.951,8.815) U6(-2.729,9.047) U7(-3.379,9.047) U8(-4.029,9.047) U9(-4.679,9.047) U10(-5.33,9.047) U11(-5.98,9.047) U12(-6.63,9.047) U13(-7.28,9.047) U63(-35.427,8.89) U64(-36.077,8.89) U65(-36.727,8.89) U66(-37.377,8.89) U67(-38.028,8.89) U68(-38.678,8.89) U69(-39.328,8.89) U70(-39.978,8.89) U71(-40.629,8.89) V3(-1.626,9.478) V15(-8.126,9.629) V16(-8.776,9.629) V17(-9.426,9.629) V18(-10.077,9.629) V19(-10.727,9.629) V20(-11.377,9.629) V21(-12.027,9.629) V62(-34.958,9.347) W4(-1.951,10.141) W6(-2.729,10.114) W7(-3.379,10.114) W8(-4.029,10.114) W9(-4.679,10.114) W10(-5.33,10.114) W11(-5.98,10.114) W12(-6.63,10.114) W13(-7.28,10.114) W63(-35.427,9.804) W64(-36.077,9.804) W65(-36.727,9.804) W66(-37.377,9.804) W67(-38.028,9.804) W68(-38.678,9.804) W69(-39.328,9.804) W70(-39.978,9.804) W71(-40.629,9.804) Y15(-8.126,10.467) Y16(-8.776,10.467) Y17(-9.426,10.467) Y18(-10.077,10.467) Y19(-10.727,10.467) Y20(-11.377,10.467) Y21(-12.027,10.467) Y62(-34.958,10.261)
  oval 0.254x0.343 smd: A6(-2.847,0.325) A7(-3.523,0) A9(-4.65,0) A10(-5.325,0.325) A11(-6.001,0) A13(-7.128,0) A14(-7.803,0.325) A15(-8.479,0) A17(-9.606,0) A18(-10.281,0.325) A19(-10.957,0) A21(-12.084,0) A22(-12.759,0.325) A23(-13.435,0) A25(-14.562,0) A26(-15.237,0.325) A27(-15.913,0) A29(-17.04,0) A30(-17.715,0.325) A31(-18.391,0) A33(-19.518,0) A34(-20.194,0.325) A36(-20.869,0) A38(-21.996,0) A39(-22.672,0.325) A40(-23.347,0) A42(-24.474,0) A44(-25.15,0.325) A45(-25.825,0) A47(-26.952,0) A48(-27.628,0.325) A50(-28.303,0) A52(-29.43,0) A53(-30.106,0.325) A54(-30.781,0) A56(-31.908,0) A58(-32.584,0.325) A59(-33.259,0) A61(-34.386,0) A62(-35.062,0.325) A63(-35.737,0) A65(-36.864,0) A66(-37.54,0.325) A67(-38.215,0) AY7(-3.763,21.328) AY9(-4.898,21.328) AY11(-6.184,21.328) AY13(-7.319,21.328) AY15(-8.604,21.328) AY17(-9.74,21.328) AY20(-11.025,21.328) AY22(-12.16,21.328) AY25(-13.486,21.328) AY31(-17.167,21.328) AY33(-18.467,21.328) AY39(-22.148,21.328) AY42(-23.423,21.328) AY48(-27.103,21.328) AY50(-28.236,21.328) AY56(-31.916,21.328) AY59(-33.191,21.328) AY65(-36.872,21.328) AY67(-38.216,21.328) B7(-3.523,0.65) B9(-4.65,0.65) B11(-6.001,0.65) B13(-7.128,0.65) B15(-8.479,0.65) B17(-9.606,0.65) B19(-10.957,0.65) B21(-12.084,0.65) B23(-13.435,0.65) B25(-14.562,0.65) B27(-15.913,0.65) B29(-17.04,0.65) B31(-18.391,0.65) B33(-19.518,0.65) B36(-20.869,0.65) B38(-21.996,0.65) B40(-23.347,0.65) B42(-24.474,0.65) B45(-25.825,0.65) B47(-26.952,0.65) B50(-28.303,0.65) B52(-29.43,0.65) B54(-30.781,0.65) B56(-31.908,0.65) B59(-33.259,0.65) B61(-34.386,0.65) B63(-35.737,0.65) B65(-36.864,0.65) B67(-38.215,0.65) BA4(-1.948,22.004) BA6(-3.141,21.572) BA7(-3.705,21.978) BA9(-4.898,21.978) BA10(-5.561,21.572) BA11(-6.125,21.978) BA13(-7.319,21.978) BA14(-7.982,21.572) BA15(-8.546,21.978) BA17(-9.74,21.978) BA18(-10.403,21.572) BA20(-10.966,21.978) BA22(-12.16,21.978) BA25(-13.486,21.978) BA26(-14.149,21.653) BA27(-14.812,21.978) BA29(-15.841,21.978) BA30(-16.504,21.653) BA31(-17.167,21.978) BA33(-18.467,21.978) BA34(-19.13,21.653) BA35(-19.793,21.978) BA37(-20.822,21.978) BA38(-21.485,21.653) BA39(-22.148,21.978) BA42(-23.423,21.978) BA43(-24.086,21.653) BA44(-24.748,21.978) BA46(-25.777,21.978) BA47(-26.44,21.653) BA48(-27.103,21.978) BA50(-28.236,21.978) BA51(-28.899,21.653) BA52(-29.562,21.978) BA54(-30.59,21.978) BA55(-31.253,21.653) BA56(-31.916,21.978) BA59(-33.191,21.978) BA60(-33.854,21.653) BA61(-34.517,21.978) BA63(-35.546,21.978) BA64(-36.209,21.653) BA65(-36.872,21.978) BA66(-37.535,21.653) BA67(-38.216,21.978) BB5(-2.529,22.628) BB6(-3.141,22.303) BB7(-3.705,22.628) BB9(-4.898,22.628) BB10(-5.561,22.303) BB11(-6.125,22.628) BB13(-7.319,22.628) BB14(-7.982,22.303) BB15(-8.546,22.628) BB17(-9.74,22.628) BB18(-10.403,22.303) BB20(-10.966,22.628) BB22(-12.16,22.628) BB23(-12.849,22.222) BB25(-13.486,22.628) BB26(-14.149,22.303) BB27(-14.812,22.628) BB29(-15.841,22.628) BB30(-16.504,22.303) BB31(-17.167,22.628) BB32(-17.83,22.222) BB33(-18.467,22.628) BB34(-19.13,22.303) BB35(-19.793,22.628) BB37(-20.822,22.628) BB38(-21.485,22.303) BB39(-22.148,22.628) BB41(-22.785,22.222) BB42(-23.423,22.628) BB43(-24.086,22.303) BB44(-24.748,22.628) BB46(-25.777,22.628) BB47(-26.44,22.303) BB48(-27.103,22.628) BB50(-28.236,22.628) BB51(-28.899,22.303) BB52(-29.562,22.628) BB54(-30.59,22.628) BB55(-31.253,22.303) BB56(-31.916,22.628) BB57(-32.554,22.222) BB59(-33.191,22.628) BB60(-33.854,22.303) BB61(-34.517,22.628) BB63(-35.546,22.628) BB64(-36.209,22.303) BB65(-36.872,22.628) BB66(-37.535,22.303) BB67(-38.216,22.628)
  oval 0.343x0.254 smd: AA1(-0.325,10.804) AB1(0,11.467) AB2(-0.65,11.467) AB3(-1.3,11.467) AC1(-0.325,12.13) AC2(-0.975,12.13) AD1(0,12.792) AD2(-0.65,12.792) AD3(-1.3,12.792) AF1(-0.325,13.455) AF70(-39.978,13.154) AF71(-40.629,13.154) AG1(0,14.118) AG2(-0.65,14.118) AG3(-1.3,14.118) AG70(-39.653,13.817) AG71(-40.303,13.817) AH1(-0.325,14.781) AH2(-0.975,14.781) AH68(-38.678,14.48) AH69(-39.328,14.48) AH70(-39.978,14.48) AH71(-40.629,14.48) AJ1(0,15.444) AJ2(-0.65,15.444) AJ3(-1.3,15.444) AK70(-40.303,15.143) AL1(-0.325,16.107) AL68(-38.678,15.806) AL69(-39.328,15.806) AL70(-39.978,15.806) AL71(-40.629,15.806) AM1(0,16.77) AM2(-0.65,16.77) AM3(-1.3,16.77) AM70(-39.653,16.469) AM71(-40.303,16.469) AN1(-0.325,17.433) AN2(-0.975,17.433) AN70(-39.978,17.132) AN71(-40.629,17.132) AP1(0,18.096) AP2(-0.65,18.096) AP3(-1.3,18.096) AR70(-39.978,18.16) AR71(-40.629,18.16) AT1(-0.325,18.759) AT70(-39.653,18.823) AT71(-40.303,18.823) AU1(0,19.422) AU2(-0.65,19.422) AU3(-1.3,19.422) AU68(-38.678,19.461) AU69(-39.328,19.486) AU70(-39.978,19.486) AU71(-40.629,19.486) AV1(0,20.142) AV2(-0.95,20.113) AV71(-40.629,20.215) AW2(-0.625,20.677) AW3(-1.275,20.677) E70(-39.978,2.305) E71(-40.629,2.413) F1(-0.325,2.848) F70(-39.526,2.994) F71(-40.176,2.931) G1(0,3.511) G2(-0.65,3.511) G3(-1.3,3.511) G70(-39.978,3.555) G71(-40.629,3.555) H1(-0.325,4.174) H2(-0.975,4.174) H70(-39.653,4.218) H71(-40.303,4.218) J1(0,4.837) J2(-0.65,4.837) J3(-1.3,4.837) J69(-39.328,4.881) J70(-39.978,4.881) J71(-40.629,4.881) K71(-40.303,5.57) L1(-0.325,5.5) M1(0,6.163) M2(-0.65,6.163) M3(-1.3,6.163) N1(-0.325,6.826) N2(-0.975,6.826) P1(0,7.489) P2(-0.65,7.489) P3(-1.3,7.489) T1(-0.325,8.152) U1(0,8.815) U2(-0.65,8.815) U3(-1.3,8.815) V1(-0.325,9.478) V2(-0.975,9.478) W1(0,10.141) W2(-0.65,10.141) W3(-1.3,10.141)
